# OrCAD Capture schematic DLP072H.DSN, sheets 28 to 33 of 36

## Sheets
28 PAGE33 - SECONDARY PWR & CAP: size A2
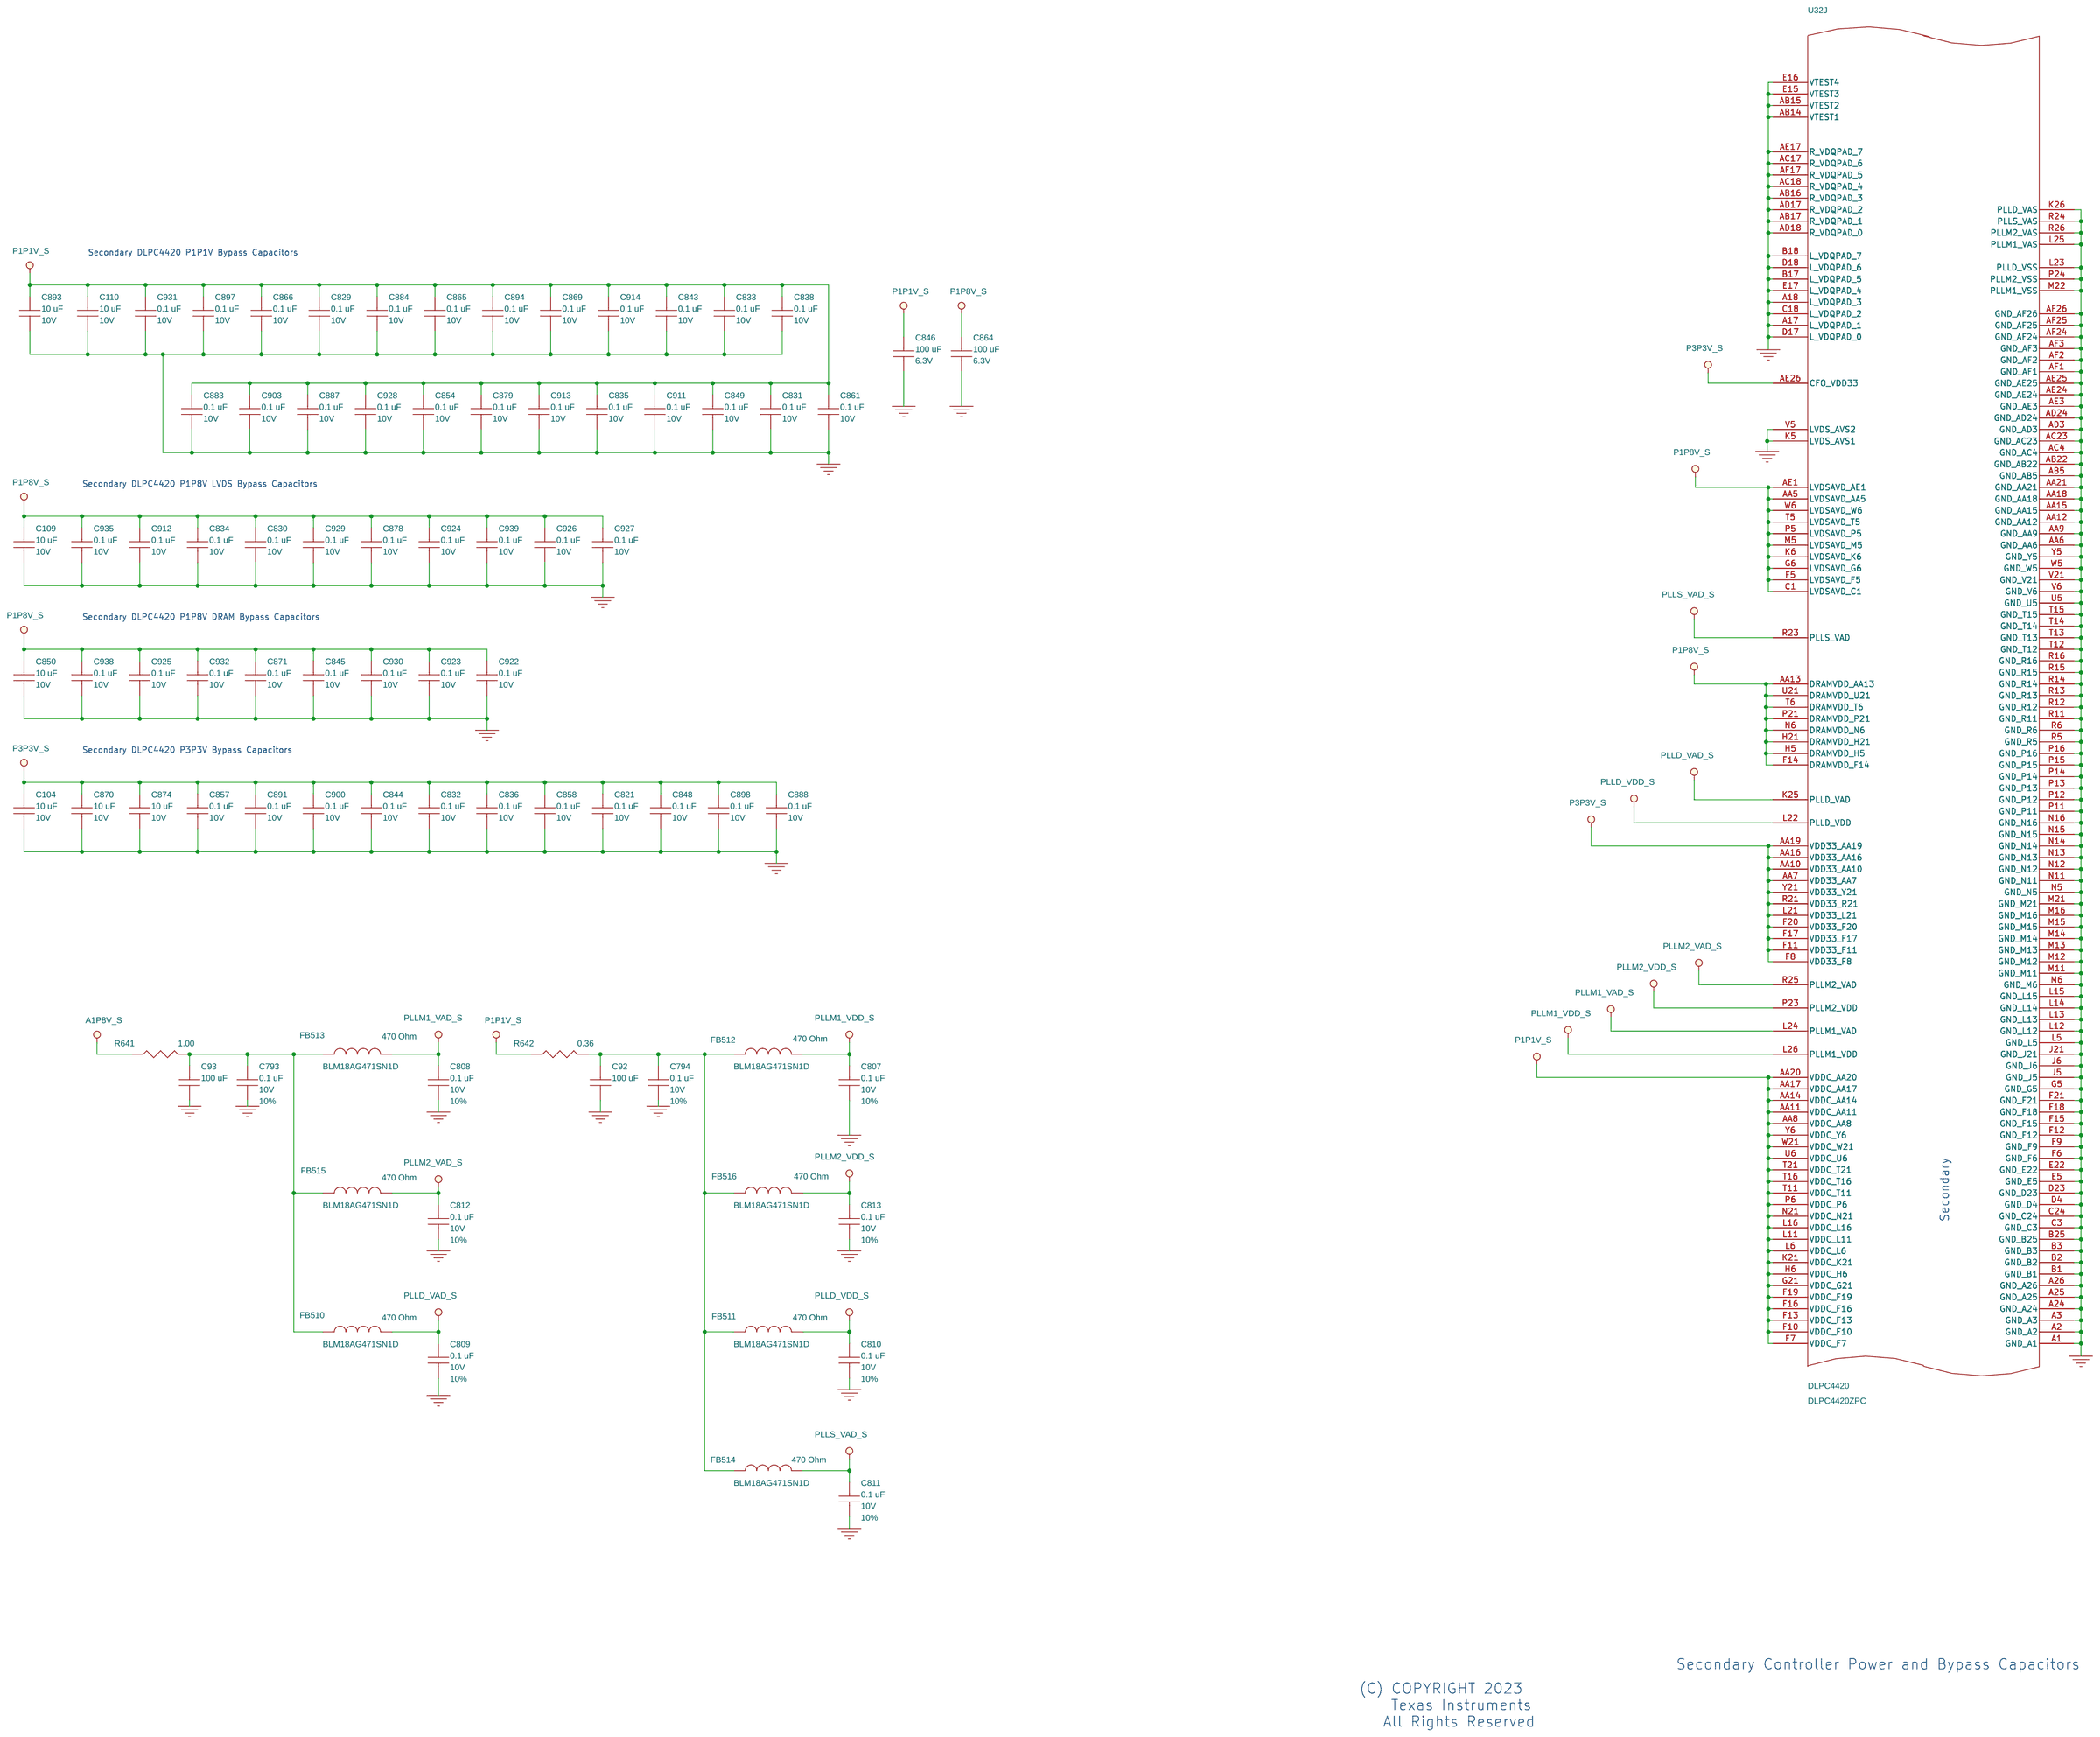
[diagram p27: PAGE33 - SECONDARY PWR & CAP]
29 PAGE36 - IMPORTANT NOTICE
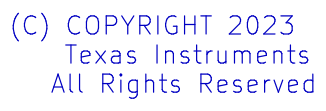
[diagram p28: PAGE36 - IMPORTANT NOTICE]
30 PAGE03 - FPGA FRONT END I/F: size A3
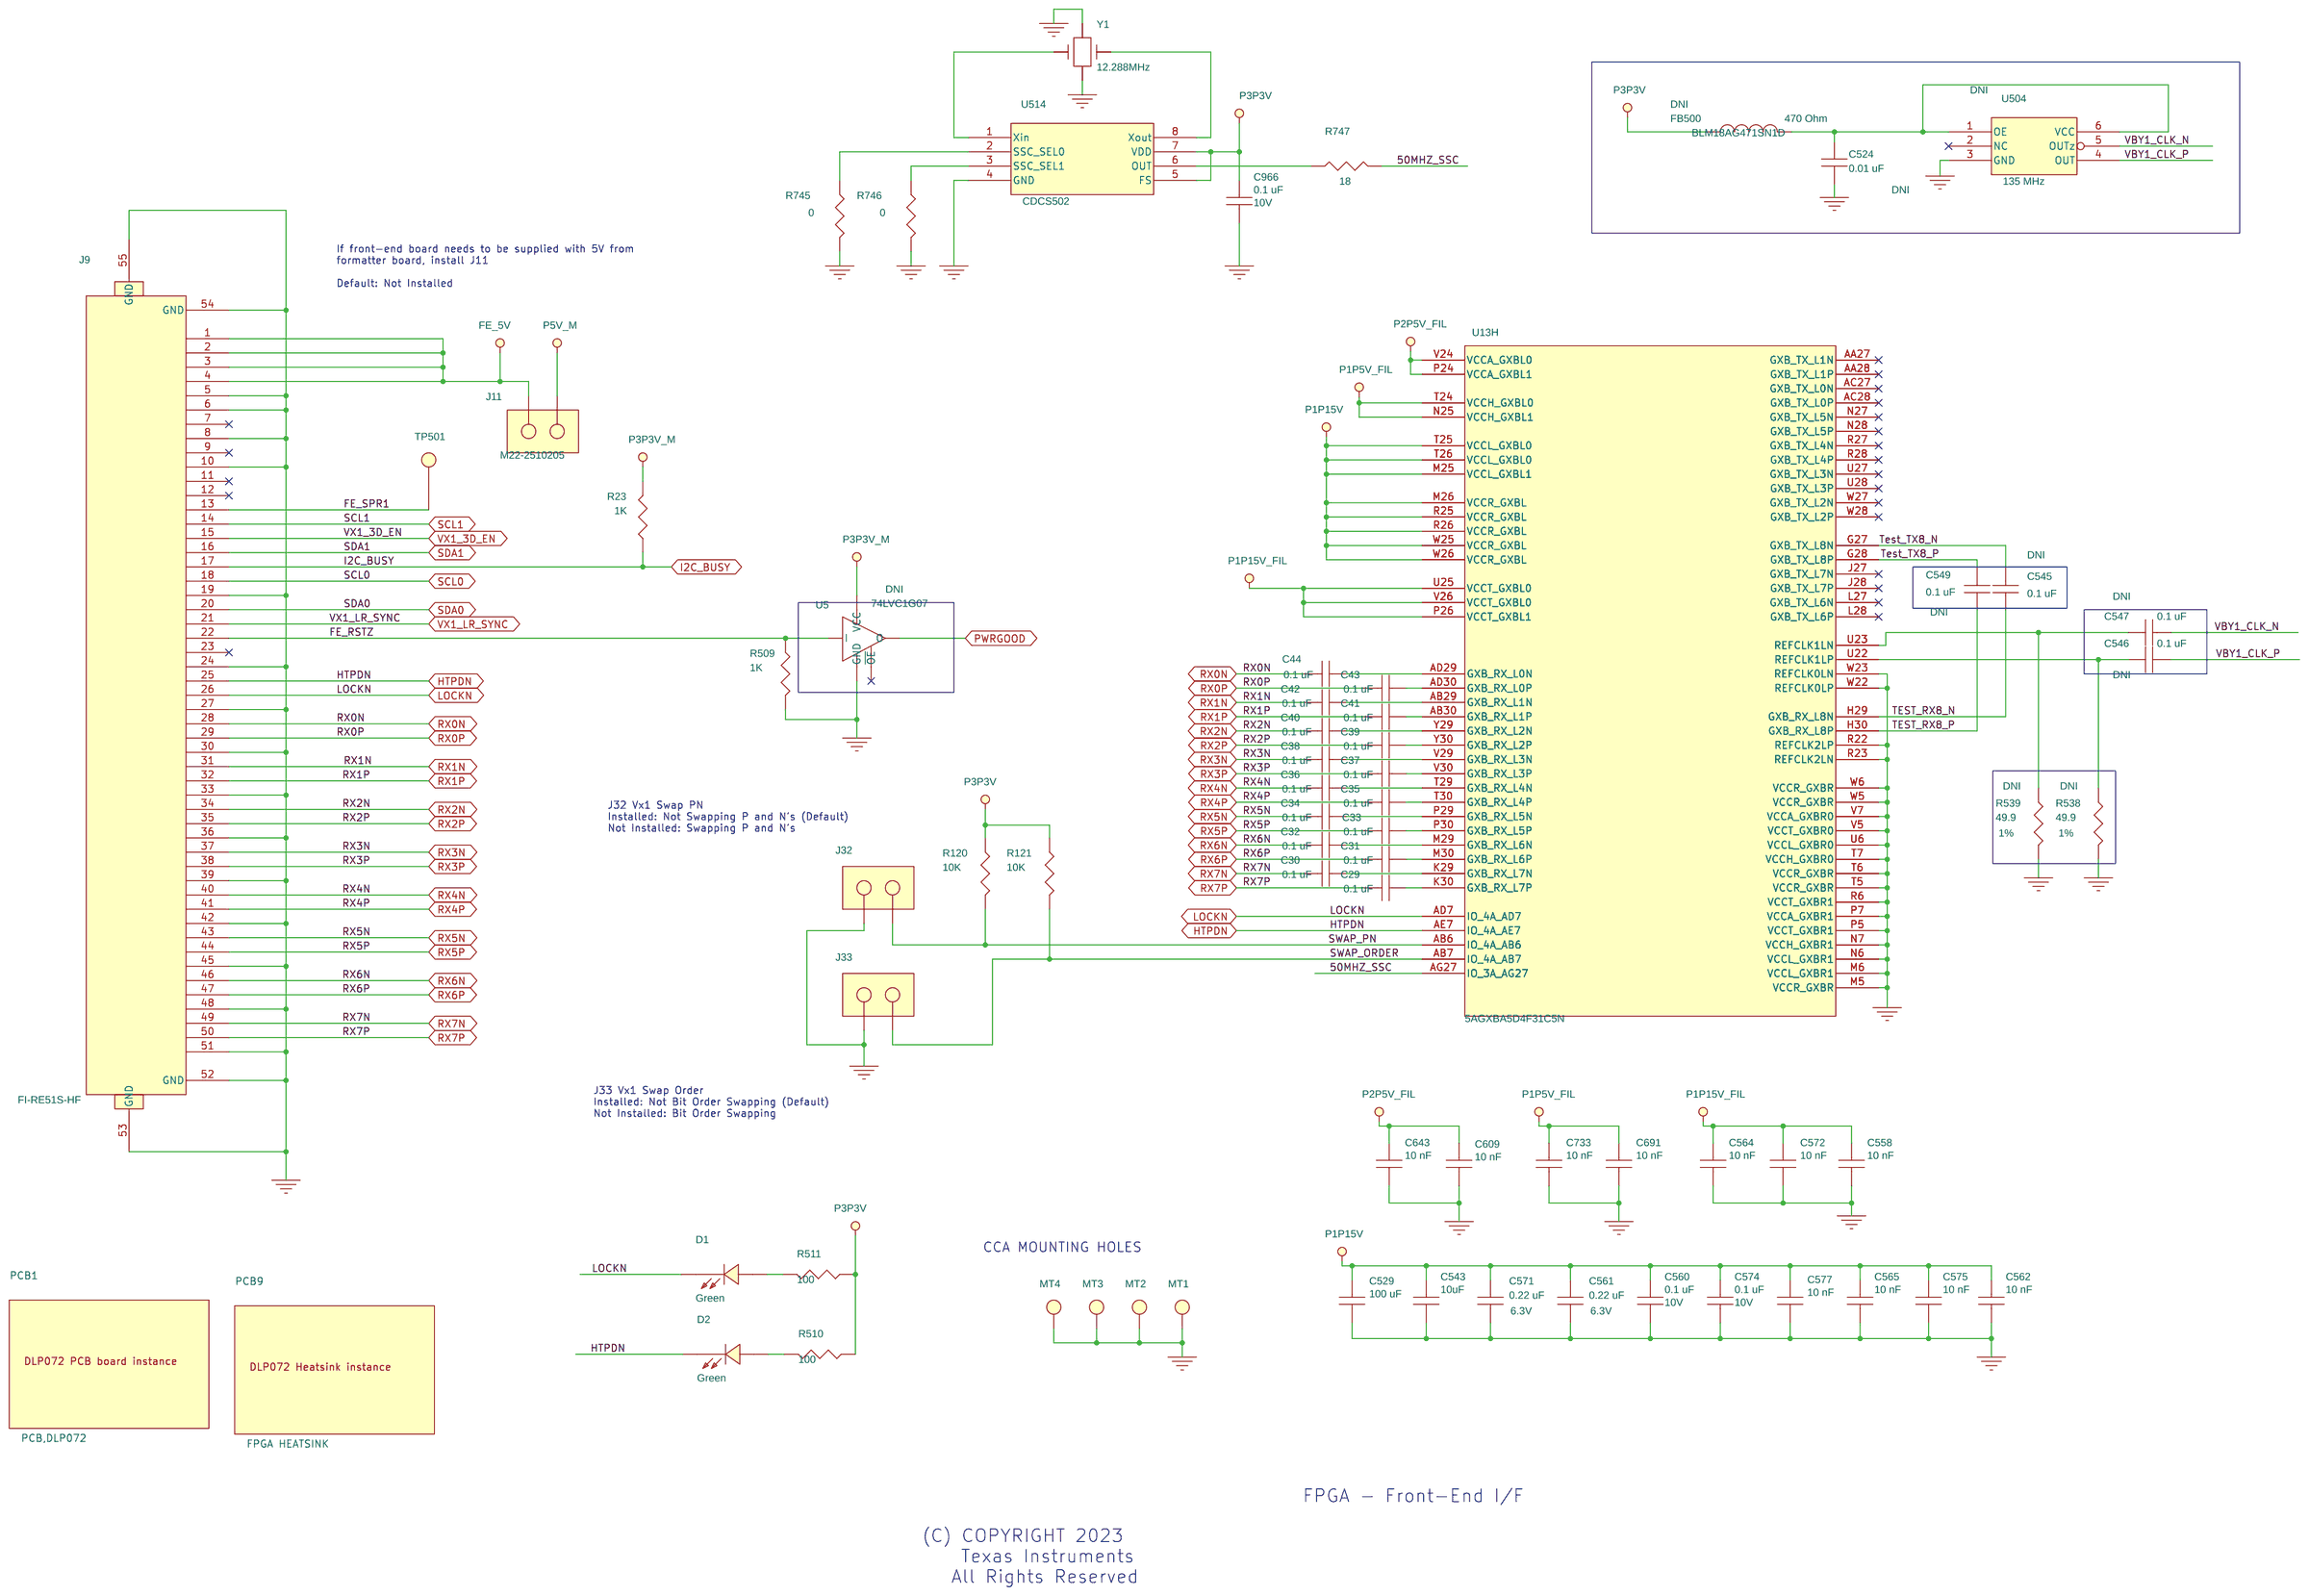
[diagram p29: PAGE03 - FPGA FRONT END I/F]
31 PAGE07 - FPGA Video I/F: size A3
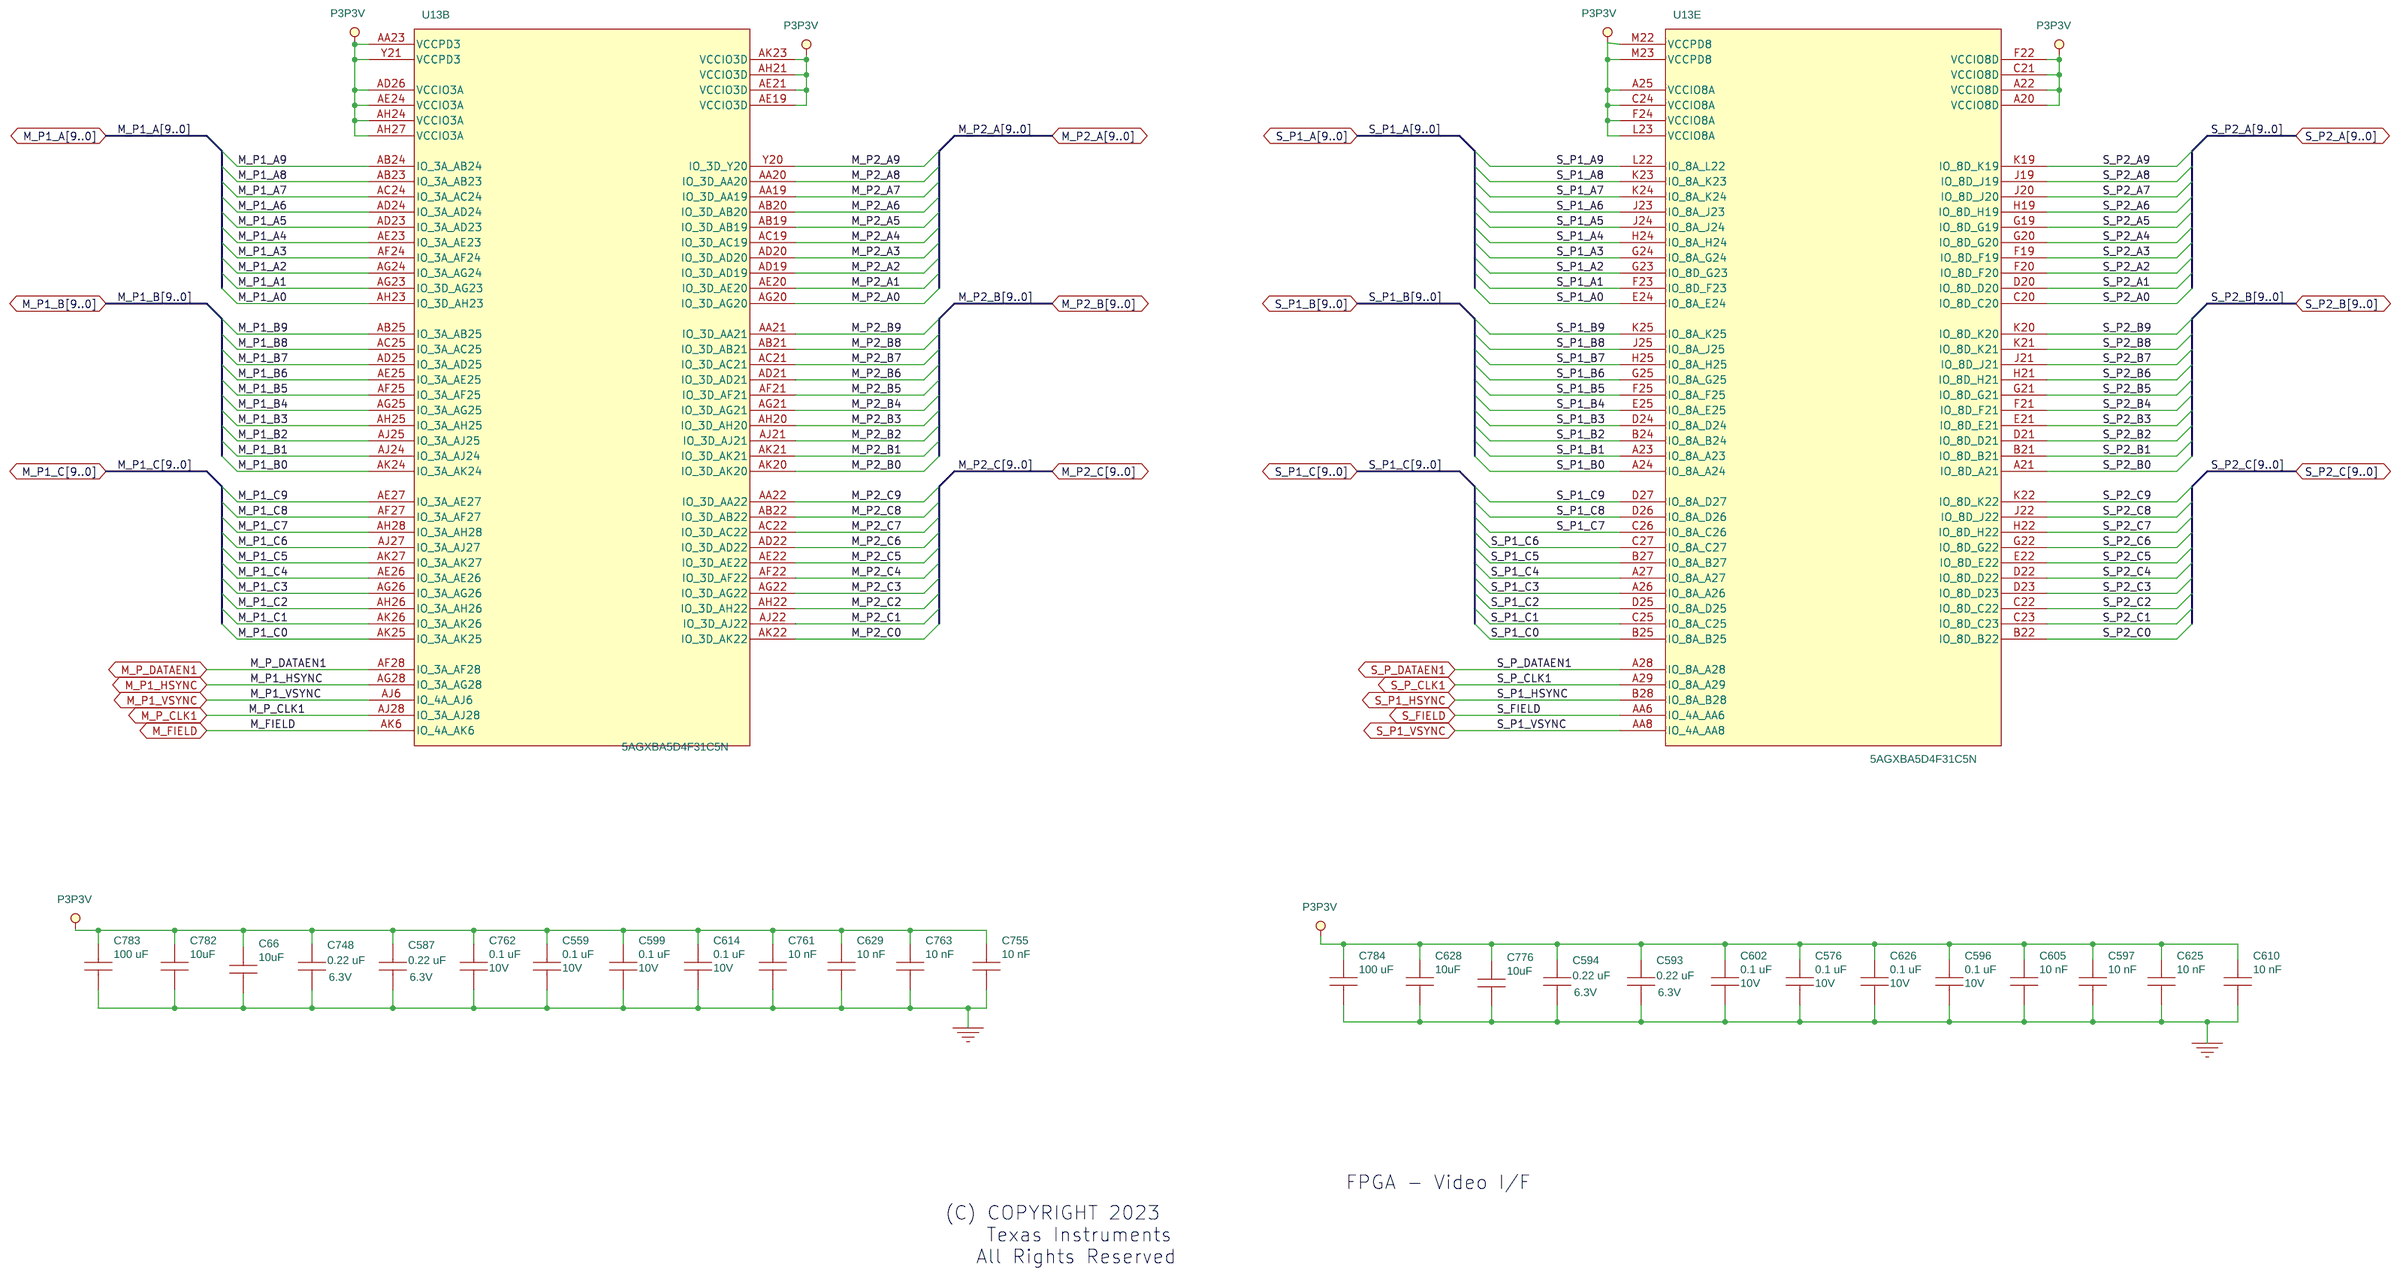
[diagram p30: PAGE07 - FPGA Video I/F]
32 PAGE04 - FPGA DDR3 I/F: size A3
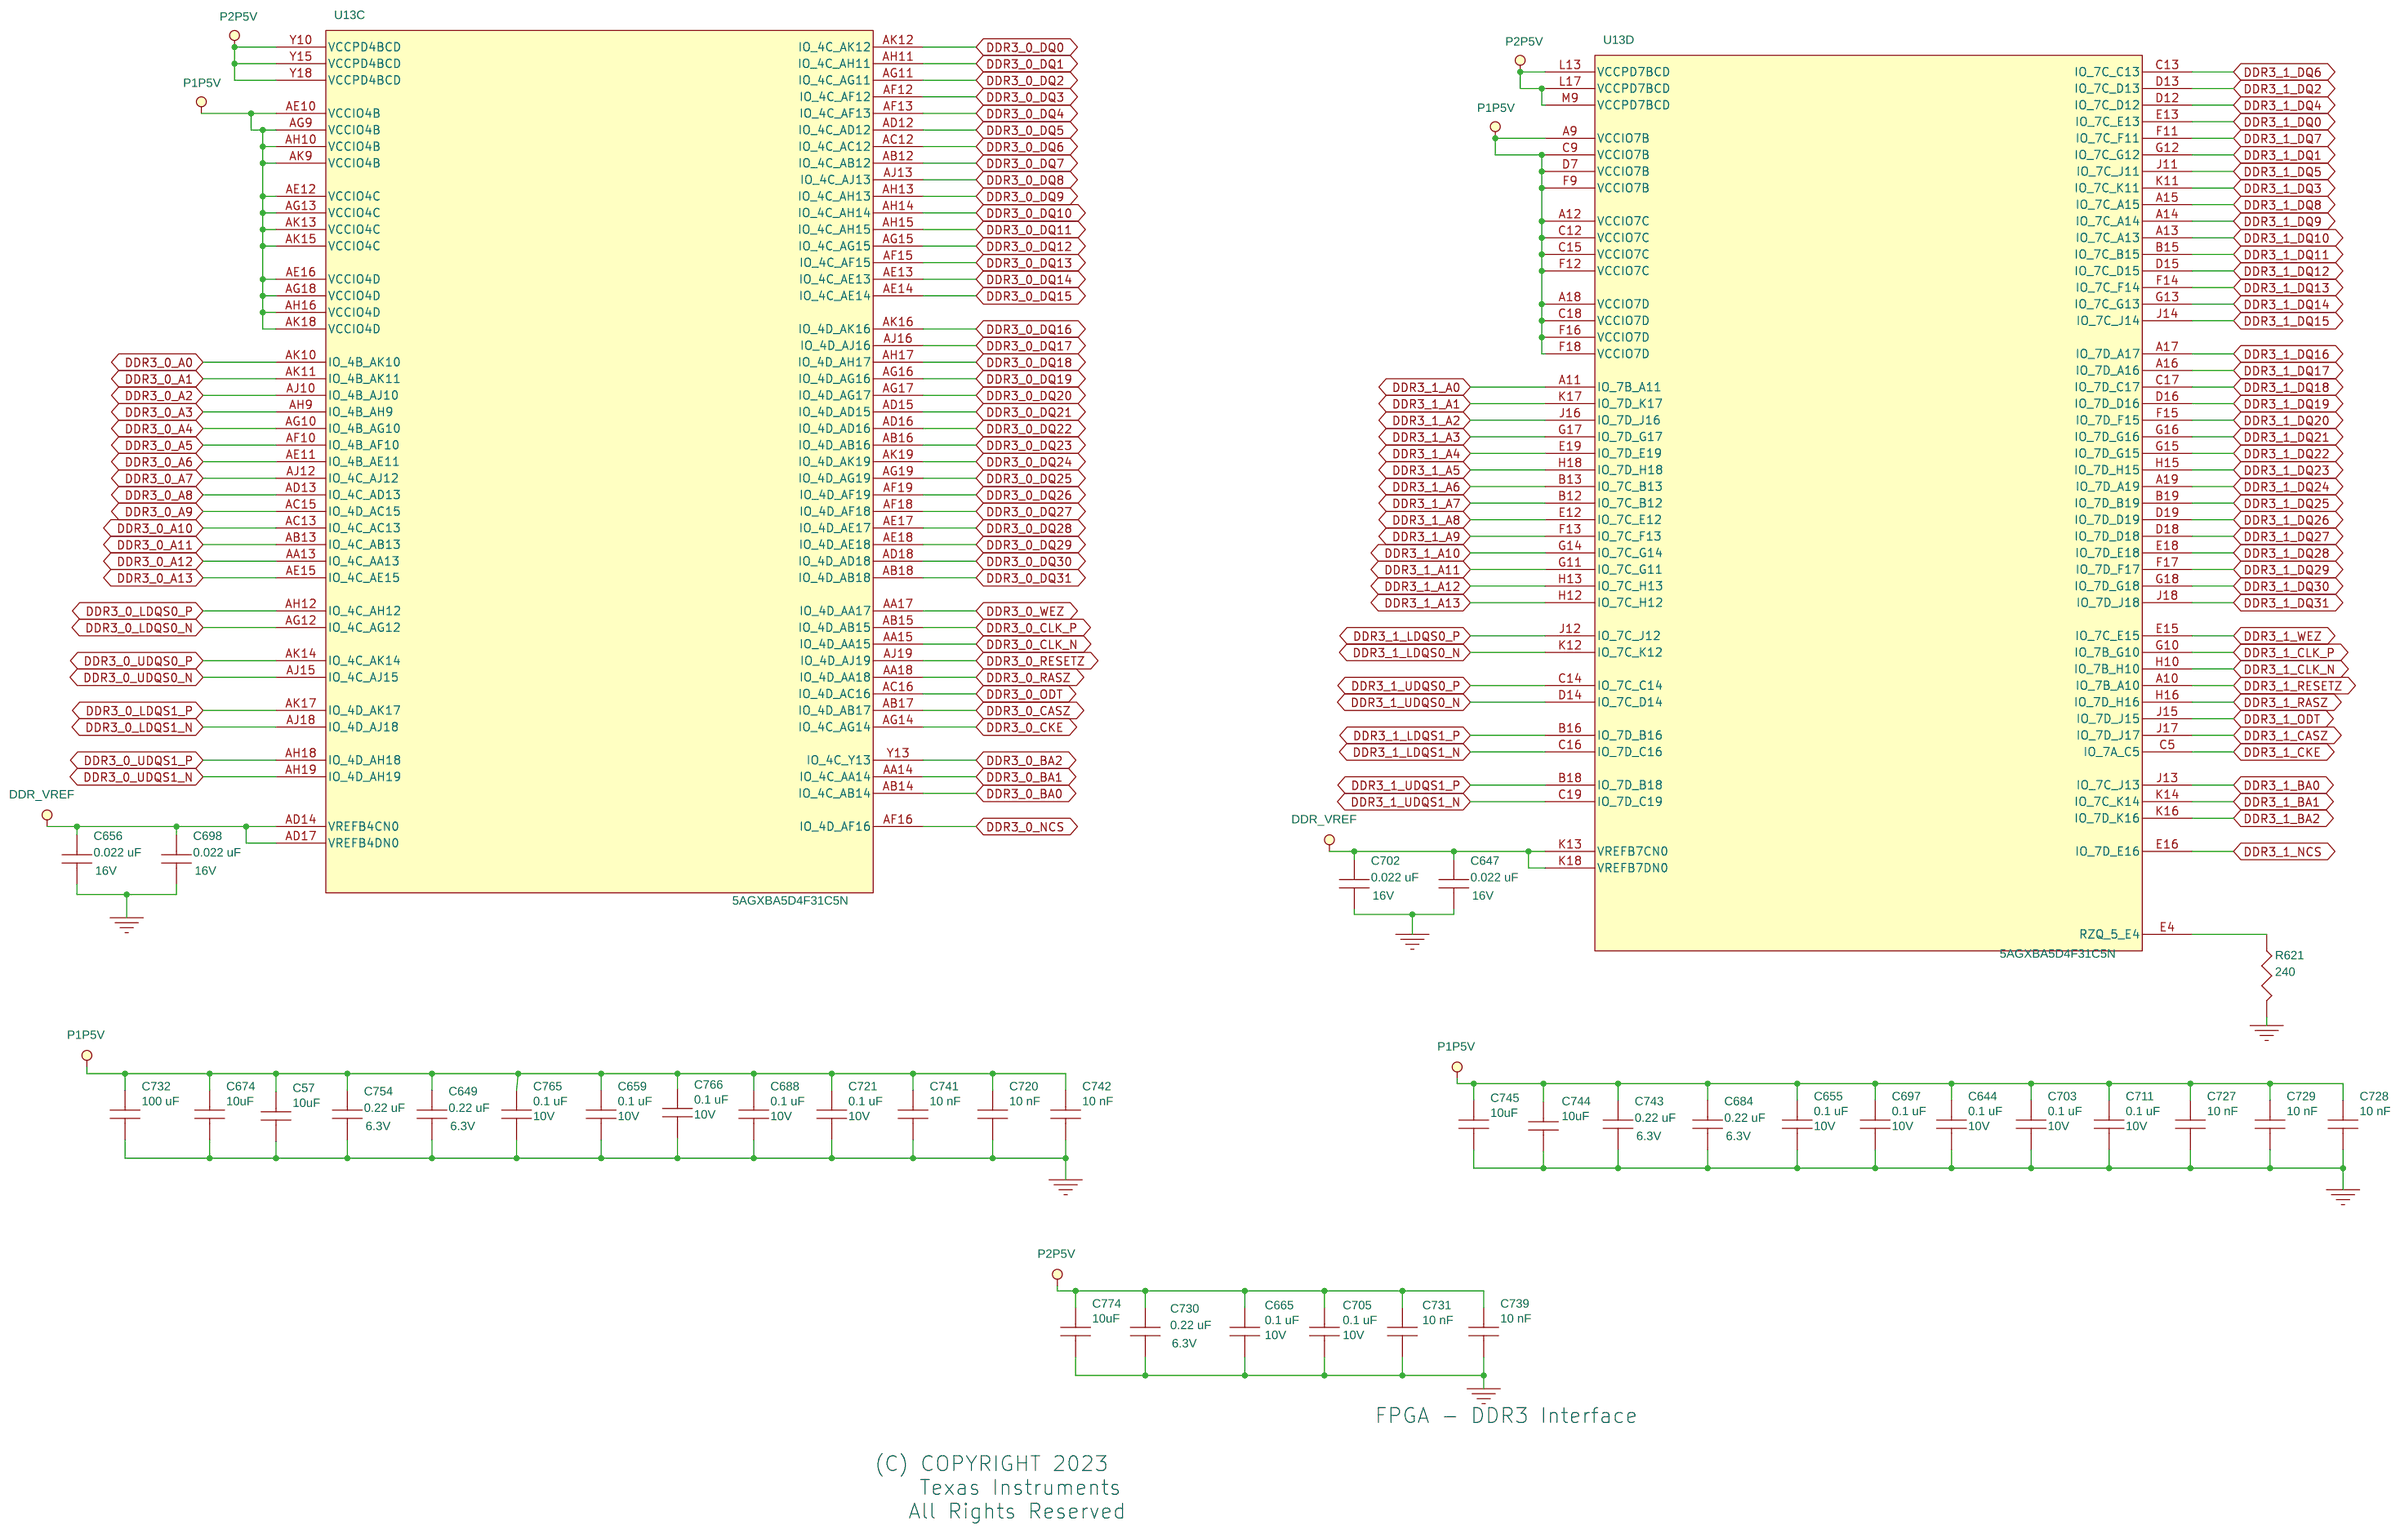
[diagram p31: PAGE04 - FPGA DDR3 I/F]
33 PAGE08 - FPGA Prog/Test MUX: size A3
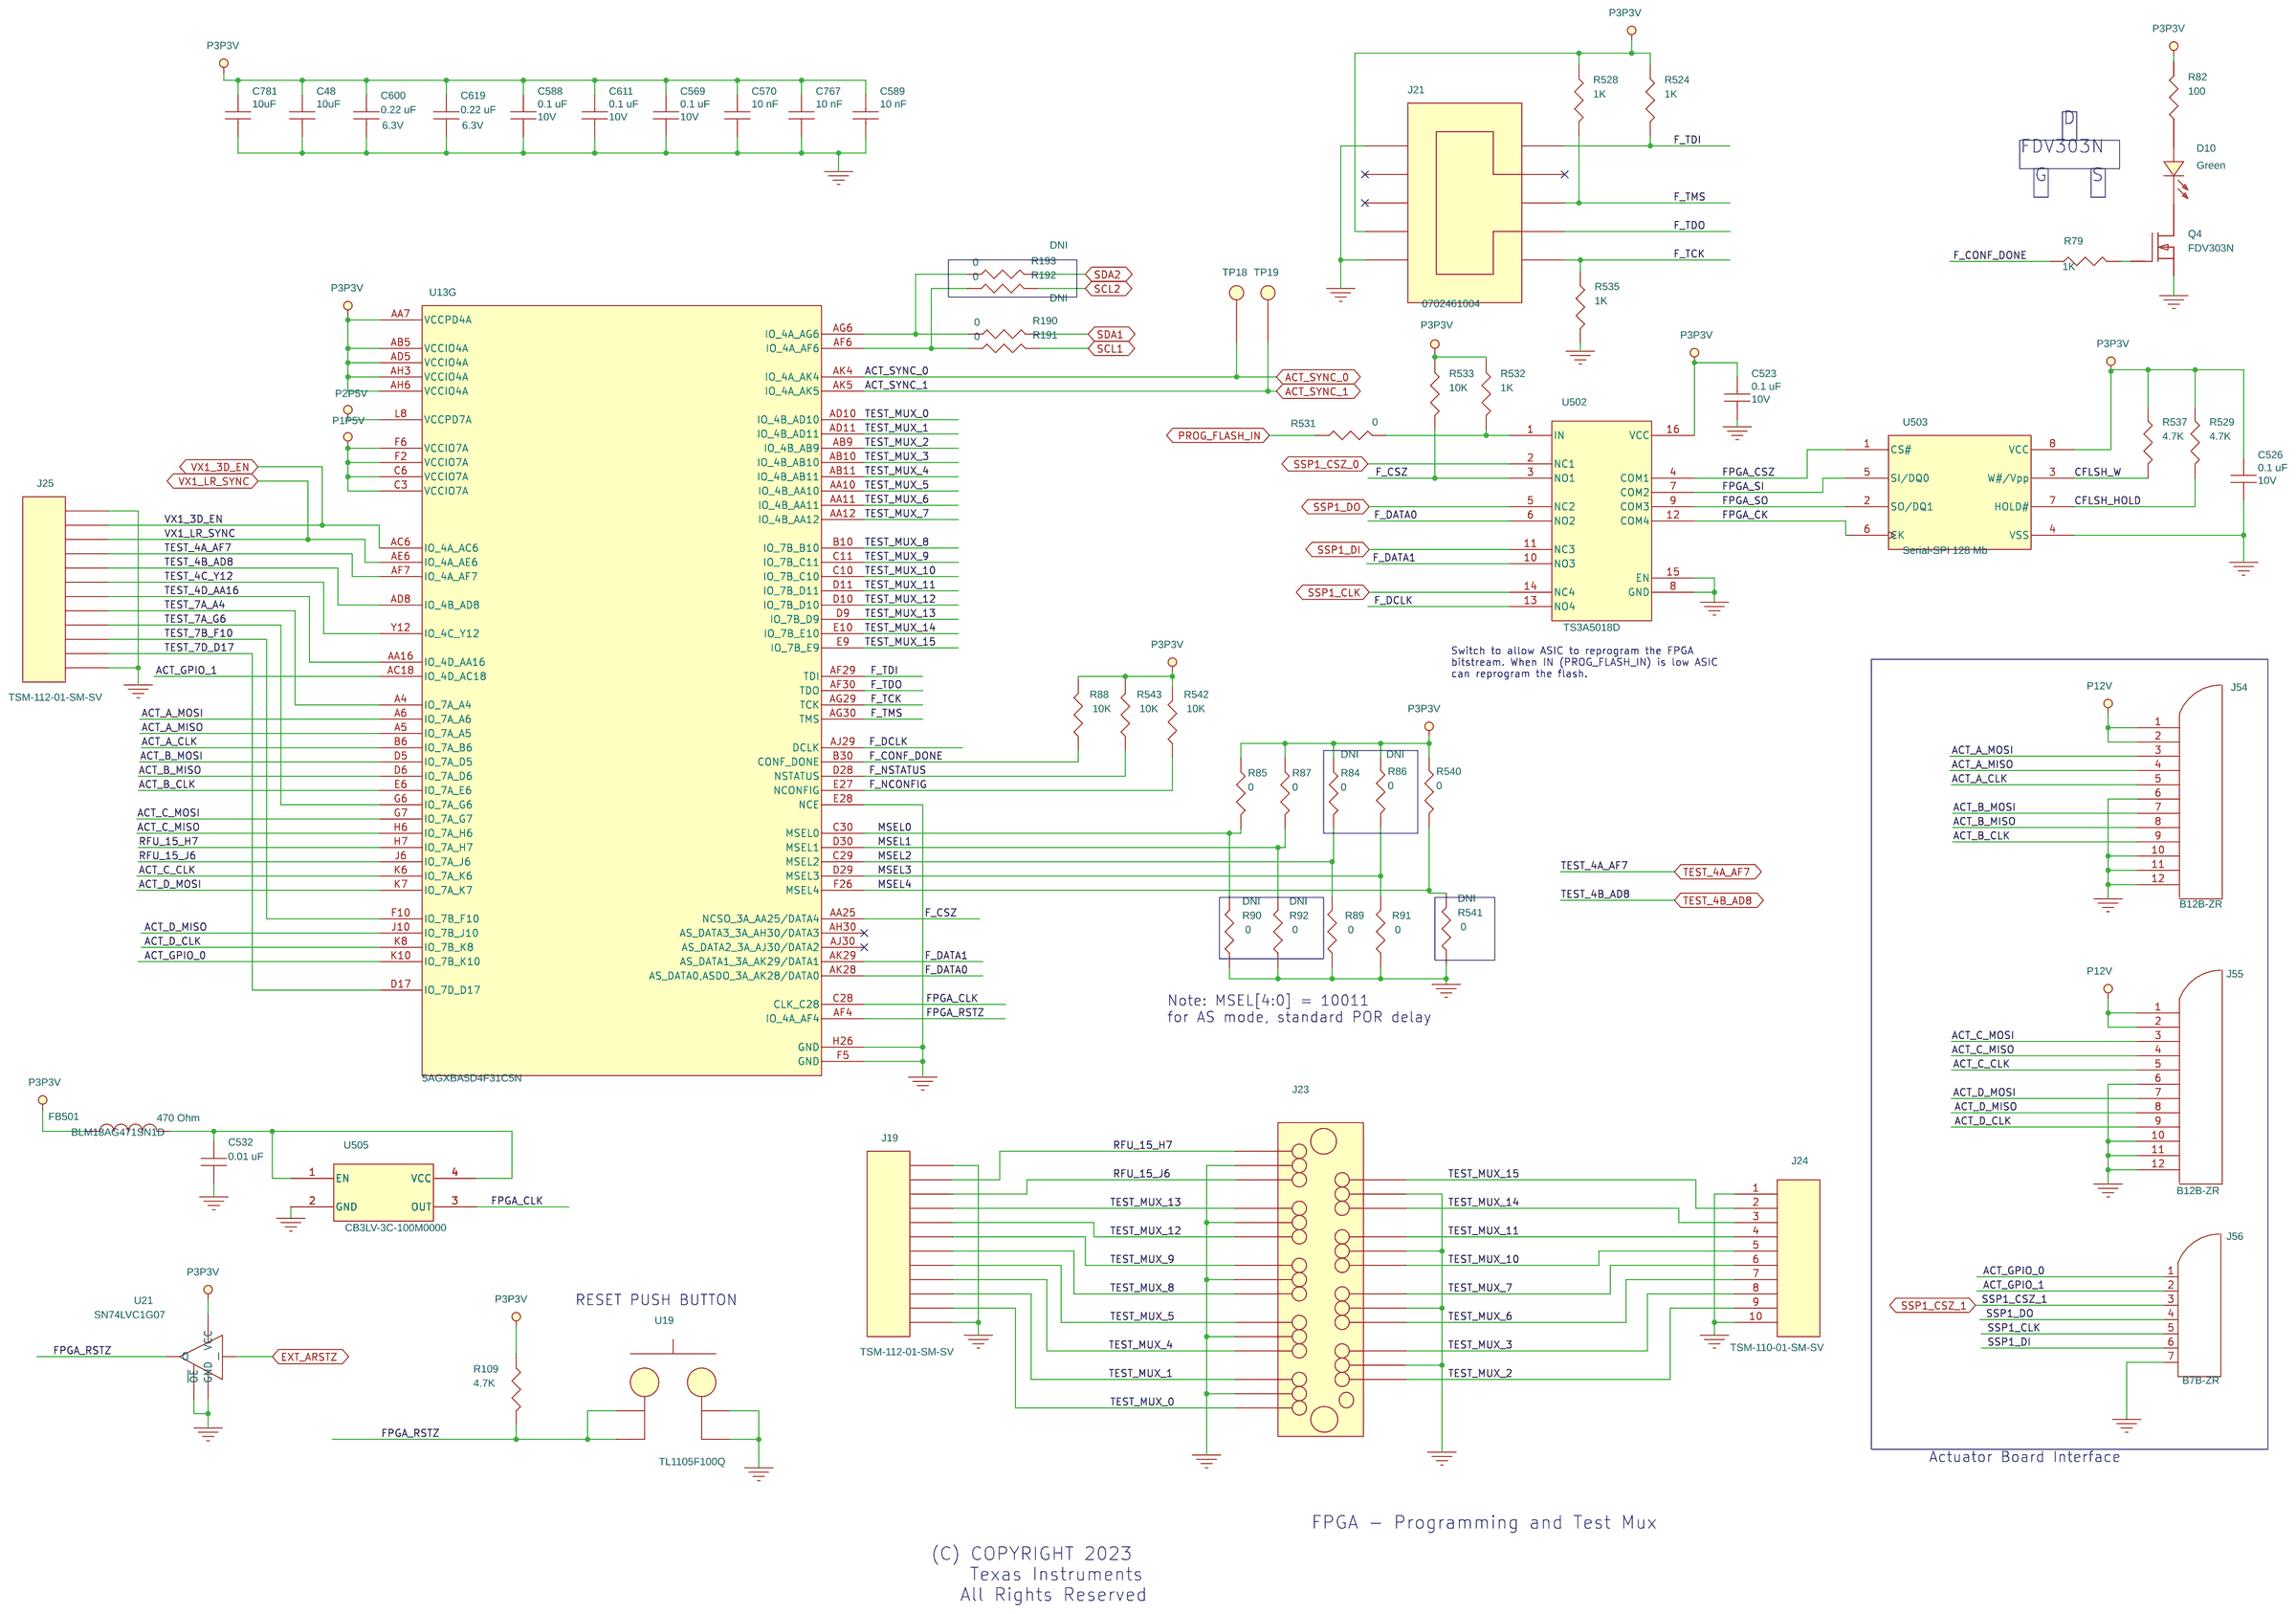
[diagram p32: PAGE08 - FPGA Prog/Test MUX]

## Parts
sheet PAGE03 - FPGA FRONT END I/F
C29  0.1 uF  [CAP_0402]
C30  0.1 uF  [CAP_0402]
C31  0.1 uF  [CAP_0402]
C32  0.1 uF  [CAP_0402]
C33  0.1 uF  [CAP_0402]
C34  0.1 uF  [CAP_0402]
C35  0.1 uF  [CAP_0402]
C36  0.1 uF  [CAP_0402]
C37  0.1 uF  [CAP_0402]
C38  0.1 uF  [CAP_0402]
C39  0.1 uF  [CAP_0402]
C40  0.1 uF  [CAP_0402]
C41  0.1 uF  [CAP_0402]
C42  0.1 uF  [CAP_0402]
C43  0.1 uF  [CAP_0402]
C44  0.1 uF  [CAP_0402]
C524  0.01 uF  [CAP_0603]
C529  100 uF  [CAP_1206]
C543  10uF  [CAP_0402]
C545  0.1 uF  [CAP_0402]
C546  0.1 uF  [CAP_0402]
C547  0.1 uF  [CAP_0402]
C549  0.1 uF  [CAP_0402]
C558  10 nF  [CAP_0402]
C560  0.1 uF  [CAP_0402]
C561  0.22 uF  [CAP_0402]
C562  10 nF  [CAP_0402]
C564  10 nF  [CAP_0402]
C565  10 nF  [CAP_0402]
C571  0.22 uF  [CAP_0402]
C572  10 nF  [CAP_0402]
C574  0.1 uF  [CAP_0402]
C575  10 nF  [CAP_0402]
C577  10 nF  [CAP_0402]
C609  10 nF  [CAP_0402]
C643  10 nF  [CAP_0402]
C691  10 nF  [CAP_0402]
C733  10 nF  [CAP_0402]
C966  0.1 uF  [CAP_0402]
D1  Green  [D_0603]
D2  Green  [D_0603]
FB500  470 Ohm  [FLTR_0603]
J9  FI-RE51S-HF  [FI-R51-RA]
J11  HDR_2  [HDR2_2MM]
J32  HDR_2  [HDR2_2MM]
J33  HDR_2  [HDR2_2MM]
MT1  MOUNTING HOLE  [MH276-157GND]
MT2  MOUNTING HOLE  [MH276-157GND]
MT3  MOUNTING HOLE  [MH276-157GND]
MT4  MOUNTING HOLE  [MH276-157GND]
PCB1  PCB,DLP072
PCB9  FPGA HEATSINK
R23  1K  [RES_0402]
R120  10K  [RES_0402]
R121  10K  [RES_0402]
R509  1K  [RES_0402]
R510  100  [RES_0402]
R511  100  [RES_0402]
R538  49.9  [RES_0402]
R539  49.9  [RES_0402]
R745  0  [RES_0402]
R746  0  [RES_0402]
R747  18  [RES_0402]
TP501  Testpoint  [TP]
U5  74LVC1G07  [SOT23-DBV_TI]
U504  135 MHz  [5x7_6pad]
U514  CDCS502  [8-TSSOP]
Y1  12.288MHz  [ABM8G-12p288MHZ-4Y-T3]
sheet PAGE04 - FPGA DDR3 I/F
C57  10uF  [CAP_0402]
C644  0.1 uF  [CAP_0402]
C647  0.022 uF  [CAP_0402]
C649  0.22 uF  [CAP_0402]
C655  0.1 uF  [CAP_0402]
C656  0.022 uF  [CAP_0402]
C659  0.1 uF  [CAP_0402]
C665  0.1 uF  [CAP_0402]
C674  10uF  [CAP_0402]
C684  0.22 uF  [CAP_0402]
C688  0.1 uF  [CAP_0402]
C697  0.1 uF  [CAP_0402]
C698  0.022 uF  [CAP_0402]
C702  0.022 uF  [CAP_0402]
C703  0.1 uF  [CAP_0402]
C705  0.1 uF  [CAP_0402]
C711  0.1 uF  [CAP_0402]
C720  10 nF  [CAP_0402]
C721  0.1 uF  [CAP_0402]
C727  10 nF  [CAP_0402]
C728  10 nF  [CAP_0402]
C729  10 nF  [CAP_0402]
C730  0.22 uF  [CAP_0402]
C731  10 nF  [CAP_0402]
C732  100 uF  [CAP_1206]
C739  10 nF  [CAP_0402]
C741  10 nF  [CAP_0402]
C742  10 nF  [CAP_0402]
C743  0.22 uF  [CAP_0402]
C744  10uF  [CAP_0402]
C745  10uF  [CAP_0402]
C754  0.22 uF  [CAP_0402]
C765  0.1 uF  [CAP_0402]
C766  0.1 uF  [CAP_0402]
C774  10uF  [CAP_0402]
R621  240  [RES_0402]
sheet PAGE07 - FPGA Video I/F
C66  10uF  [CAP_0402]
C559  0.1 uF  [CAP_0402]
C576  0.1 uF  [CAP_0402]
C587  0.22 uF  [CAP_0402]
C593  0.22 uF  [CAP_0402]
C594  0.22 uF  [CAP_0402]
C596  0.1 uF  [CAP_0402]
C597  10 nF  [CAP_0402]
C599  0.1 uF  [CAP_0402]
C602  0.1 uF  [CAP_0402]
C605  10 nF  [CAP_0402]
C610  10 nF  [CAP_0402]
C614  0.1 uF  [CAP_0402]
C625  10 nF  [CAP_0402]
C626  0.1 uF  [CAP_0402]
C628  10uF  [CAP_0402]
C629  10 nF  [CAP_0402]
C748  0.22 uF  [CAP_0402]
C755  10 nF  [CAP_0402]
C761  10 nF  [CAP_0402]
C762  0.1 uF  [CAP_0402]
C763  10 nF  [CAP_0402]
C776  10uF  [CAP_0402]
C782  10uF  [CAP_0402]
C783  100 uF  [CAP_1206]
C784  100 uF  [CAP_1206]
sheet PAGE08 - FPGA Prog/Test MUX
C48  10uF  [CAP_0402]
C523  0.1 uF  [CAP_0402]
C526  0.1 uF  [CAP_0402]
C532  0.01 uF  [CAP_0603]
C569  0.1 uF  [CAP_0402]
C570  10 nF  [CAP_0402]
C588  0.1 uF  [CAP_0402]
C589  10 nF  [CAP_0402]
C600  0.22 uF  [CAP_0402]
C611  0.1 uF  [CAP_0402]
C619  0.22 uF  [CAP_0402]
C767  10 nF  [CAP_0402]
C781  10uF  [CAP_0402]
D10  Green  [D_0603]
FB501  470 Ohm  [FLTR_0603]
J19  CON12  [CONN12-SMT-TSM-112-SV_SAMTEC]
J21  0702461004  [10POS-2ROWS-2p54mm]
J23  EM,CONN,P6419 Footprint  [TEKP6419]
J24  TSM-110-01-SM-SV  [CN-10-2_54MM]
J25  CON12  [CONN12-SMT-TSM-112-SV_SAMTEC]
J54  B12B-ZR  [B12B-ZR]
J55  B12B-ZR  [B12B-ZR]
J56  B7B-ZR  [B7B-ZR]
Q4  FDV303N  [SOT-23]
R79  1K  [RES_0402]
R82  100  [RES_0402]
R84  0  [RES_0402]
R85  0  [RES_0402]
R86  0  [RES_0402]
R87  0  [RES_0402]
R88  10K  [RES_0402]
R89  0  [RES_0402]
R90  0  [RES_0402]
R91  0  [RES_0402]
R92  0  [RES_0402]
R109  4.7K  [RES_0402]
R190  0  [RES_0402]
R191  0  [RES_0402]
R192  0  [RES_0402]
R193  0  [RES_0402]
R524  1K  [RES_0402]
R528  1K  [RES_0402]
R529  4.7K  [RES_0402]
R531  0  [RES_0402]
R532  1K  [RES_0402]
R533  10K  [RES_0402]
R535  1K  [RES_0402]
R537  4.7K  [RES_0402]
R540  0  [RES_0402]
R541  0  [RES_0402]
R542  10K  [RES_0402]
R543  10K  [RES_0402]
TP18  Testpoint  [TP]
TP19  Testpoint  [TP]
U19  6MM PUSH BUTTON SWITCH  [SW4-TL1105_ESWITCH]
U21  SN74LVC1G07  [SOT23-DBV_TI]
U502  TS3A5018D  [SOIC-16]
U503  Serial-SPI 128 Mb  [SO8W]
U505  CB3LV-3C-100M0000  [5x7mm]
sheet PAGE09 - FPGA POWER
U13  5AGXBA5D4F31C5N  [FBGA-896]  (sections A,B,C,D,E,F,G,H,I)
sheet PAGE16 - INPUT PWR & PMD1000
U32  DLPC4420  [BGA552-DDP4422_TI]  (sections A,B,C,D,E,F,G,H,I,J)
sheet PAGE33 - SECONDARY PWR & CAP
C92  100 uF  [CAP_1206]
C93  100 uF  [CAP_1206]
C104  10 uF  [CAP_0805]
C109  10 uF  [CAP_0805]
C110  10 uF  [CAP_0805]
C793  0.1 uF  [CAP_0402]
C794  0.1 uF  [CAP_0402]
C807  0.1 uF  [CAP_0402]
C808  0.1 uF  [CAP_0402]
C809  0.1 uF  [CAP_0402]
C810  0.1 uF  [CAP_0402]
C811  0.1 uF  [CAP_0402]
C812  0.1 uF  [CAP_0402]
C813  0.1 uF  [CAP_0402]
C821  0.1 uF  [CAP_0402]
C829  0.1 uF  [CAP_0402]
C830  0.1 uF  [CAP_0402]
C831  0.1 uF  [CAP_0402]
C832  0.1 uF  [CAP_0402]
C833  0.1 uF  [CAP_0402]
C834  0.1 uF  [CAP_0402]
C835  0.1 uF  [CAP_0402]
C836  0.1 uF  [CAP_0402]
C838  0.1 uF  [CAP_0402]
C843  0.1 uF  [CAP_0402]
C844  0.1 uF  [CAP_0402]
C845  0.1 uF  [CAP_0402]
C846  100 uF  [CAP_1206]
C848  0.1 uF  [CAP_0402]
C849  0.1 uF  [CAP_0402]
C850  10 uF  [CAP_0805]
C854  0.1 uF  [CAP_0402]
C857  0.1 uF  [CAP_0402]
C858  0.1 uF  [CAP_0402]
C861  0.1 uF  [CAP_0402]
C864  100 uF  [CAP_1206]
C865  0.1 uF  [CAP_0402]
C866  0.1 uF  [CAP_0402]
C869  0.1 uF  [CAP_0402]
C870  10 uF  [CAP_0805]
C871  0.1 uF  [CAP_0402]
C874  10 uF  [CAP_0805]
C878  0.1 uF  [CAP_0402]
C879  0.1 uF  [CAP_0402]
C883  0.1 uF  [CAP_0402]
C884  0.1 uF  [CAP_0402]
C887  0.1 uF  [CAP_0402]
C888  0.1 uF  [CAP_0402]
C891  0.1 uF  [CAP_0402]
C893  10 uF  [CAP_0805]
C894  0.1 uF  [CAP_0402]
C897  0.1 uF  [CAP_0402]
C898  0.1 uF  [CAP_0402]
C900  0.1 uF  [CAP_0402]
C903  0.1 uF  [CAP_0402]
C911  0.1 uF  [CAP_0402]
C912  0.1 uF  [CAP_0402]
C913  0.1 uF  [CAP_0402]
C914  0.1 uF  [CAP_0402]
C922  0.1 uF  [CAP_0402]
C923  0.1 uF  [CAP_0402]
C924  0.1 uF  [CAP_0402]
C925  0.1 uF  [CAP_0402]
C926  0.1 uF  [CAP_0402]
C927  0.1 uF  [CAP_0402]
C928  0.1 uF  [CAP_0402]
C929  0.1 uF  [CAP_0402]
C930  0.1 uF  [CAP_0402]
C931  0.1 uF  [CAP_0402]
C932  0.1 uF  [CAP_0402]
C935  0.1 uF  [CAP_0402]
C938  0.1 uF  [CAP_0402]
C939  0.1 uF  [CAP_0402]
FB510  470 Ohm  [FLTR_0603]
FB511  470 Ohm  [FLTR_0603]
FB512  470 Ohm  [FLTR_0603]
FB513  470 Ohm  [FLTR_0603]
FB514  470 Ohm  [FLTR_0603]
FB515  470 Ohm  [FLTR_0603]
FB516  470 Ohm  [FLTR_0603]
R641  1.00  [RES_0402]
R642  0.36  [RES_0402]

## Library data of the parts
C29-C44 C559 C560 C569 C574 C576 C588 C596 C599 C602 C611 C614 C626 C644 C655 C659 C665 C688 C697 C703 C705 C711 C721 C762 C765 C766 = CER_0.1UF_16V_10%_X5R_0402: CCA: 34; MFG: KEMET; Part Number: C0402C104K8RACTU; Rating: 10V; SOURCE: DIGI 399-3520-1-ND; Type: X7R
C524 = CAP_NP: Capacitor; CCA: 47; DNI: DNI; MFG: YAGEO; Part Number: CC0603KRX7R8BB103; RATING: 25V; TOLERANCE: 10%; Type: X7R
C529 C732 C783 C784 = CER_100UF_6.3V_20%_X5R_1206: CCA: 114; MFG: KEMET; Part Number: C1206C107M9PACTU; Type: X5R
C48 C57 C66 C543 C628 C674 C744 C745 C774 C776 C781 C782 = CER_10UF_6.3V_20%_X5R_0402: Part Number: CL05A106MQ5NUNC
C545-C547 C549 = CER_0.1UF_16V_10%_X5R_0402: CCA: 34; DNI: DNI; MFG: KEMET; Part Number: C0402C104K8RACTU; Rating: 10V; SOURCE: DIGI 399-3520-1-ND; Type: X7R
C558 C562 C564 C565 C570 C572 C575 C577 C589 C597 C605 C609 C610 C625 C629 C643 C691 C720 C727-C729 C731 C733 C739 C741 C742 C755 C761 C763 C767 = CER_10_nF_25V_10%_X5R_0402: Part Number: C1005X7R1H103K050BB
C561 C571 C587 C593 C594 C600 C619 C649 C684 C730 C743 C748 C754 = CAP_NP: Capacitor; CCA: 39; MFG: SAMSUNG; Part Number: CL05A224KQ5NNNC; RATING: 6.3V; SOURCE: DIGI 399-3491-1-ND; TOLERANCE: 10%; Type: X5R
C523 C526 C966 = CER_0.1UF_16V_10%_X5R_0402: CCA: 34; MFG: KEMET; Part Number: C0402C104K8RACTU; Rating: 10V; Type: X7R
D1 D2 D10 = LED_GREEN_CLEAR_0603: LED; Part Number: LTST-C190GKT
FB500 = INDUCTOR: Ferrite; CCA: 30; DNI: DNI; ICA_MFR_NAME: STEWARD; ICA_PARTNUM: $$731362$$MI0603J680R-10; MFG: MURATA; Part Number: BLM18AG471SN1D; RATING: 500mA, 100MHz; SOURCE: DIGI 490-1013-1-ND
J9 = FI-RE51S-HF: Connector, Vby1; MFG: JAE
J11 J32 J33 = HDR_0: Jumper, 1x2; CCA: 128; MFG: HARWIN; Part Number: M22-2510205; SOURCE: DIGI 952-1311-ND
MT1-MT4 = Testpoint_0: Mounting Hole; MFG: NA; Part Number: NA; SOURCE: NA
PCB1 = DLP027_1
PCB9 = DLP027_2
R23 R509 = R: Resistor; CCA: 64; ICA_MFR_NAME: PANASONIC; ICA_PARTNUM: $$1785048$$ERJ-3GSYJ102; MFG: PANASONIC; Part Number: ERJ-2GEJ102X; RATING: 1/10W; SOURCE: DIGI P1.0KJCT-ND; TOLERANCE: 5%
R88 R120 R121 R542 R543 = R: Resistor; CCA: 65; ICA_MFR_NAME: PANASONIC; ICA_PARTNUM: $$1785048$$ERJ-3GSYJ102; MFG: PANASONIC; Part Number: ERJ-2GEJ103X; RATING: 1/10W; SOURCE: DIGI P10.0KLCT-ND; TOLERANCE: 5%
R82 R510 R511 = R: Resistor; CCA: 63; ICA_MFR_NAME: PANASONIC; ICA_PARTNUM: $$1785048$$ERJ-3GSYJ102; MFG: PANASONIC; Part Number: ERJ-2GEJ101X; RATING: 1/10W; SOURCE: DIGI P100JCT-ND; TOLERANCE: 5%
R538 R539 = R: Resistor; DNI: DNI; ICA_MFR_NAME: PANASONIC; ICA_PARTNUM: $$1785048$$ERJ-3GSYJ102; MFG: BOURNS; Part Number: CR0402-FX-49R9GLF; RATING: 1/16 W; SOURCE: DIGI P10.0KLCT-ND; TOLERANCE: 1%
R85 R87 R190 R191 R531 R540 R745 R746 = R: Resistor; CCA: 62; ICA_MFR_NAME: PANASONIC; ICA_PARTNUM: $$1785048$$ERJ-3GSYJ102; MFG: PANASONIC; Part Number: ERJ-2GE0R00X; RATING: 1/10W; SOURCE: DIGI P0.0JCT-ND
R747 = R: Resistor; CCA: 62; ICA_MFR_NAME: PANASONIC; ICA_PARTNUM: $$1785048$$ERJ-3GSYJ102; MFG: PANASONIC; Part Number: ERJ-2GEJ180X; RATING: 1/10W; SOURCE: DIGI P0.0JCT-ND
TP18 TP19 TP501 = Testpoint: Test point
U5 = 74LVC1G07: IC, Non-Inverting Buffer, Open Drain; CCA: 147; DNI: DNI; MFG: TI; Part Number: SN74LVC1G07DBVR; SOURCE: DIGI 296-8485-1-ND
U504 = OSC_LVDS: OSC; DNI: DNI; MFG: ECLIPTEK; Part Number: EQRF13B2H-135.000M; Tolerance: 50 PPM
U514 = CDCS502: IC OSC CLOCK GENERATOR 8-TSSOP; Manuf Part Number: CDCS502PW; Manufacturer: Texas Instruments; Part Number: CDCS502PW
Y1 = CRYSTAL: 12.288MHz ±30ppm Crystal 10pF 80 Ohm -10°C ~ 60°C Surface Mount 4-SMD, No Lead (DFN, LCC); Manuf Part Number: ABM8G-12.288MHZ-4Y-T3; Manufacturer: Abracon; Part Number: ABM8G-12.288MHZ-4Y-T3
C647 C656 C698 C702 = CAP_NP: Capacitor; CCA: 5; MFG: AVX; Part Number: 0402YC223KAT2A; RATING: 16V; TOLERANCE: 10%; Type: X5R
R621 = R: Resistor; ALT_SYMBOLS: 0402-1MM; CCA: 73; ICA_MFR_NAME: PANASONIC; ICA_PARTNUM: $$1785048$$ERJ-3GSYJ102; MFG: PANASONIC; Part Number: ERJ-2RKF2400X; RATING: 1/10W; TOLERANCE: 1%
C532 = CAP_NP: Capacitor; CCA: 47; MFG: YAGEO; Part Number: CC0603KRX7R8BB103; RATING: 25V; TOLERANCE: 10%; Type: X7R
FB501 FB510-FB516 = INDUCTOR: Ferrite; CCA: 30; ICA_MFR_NAME: STEWARD; ICA_PARTNUM: $$731362$$MI0603J680R-10; MFG: MURATA; Part Number: BLM18AG471SN1D; RATING: 500mA, 100MHz; SOURCE: DIGI 490-1013-1-ND
J19 J25 = CON12: Header, 12 pin; CCA: 174; MFG: SAMTEC; Part Number: TSM-112-01-SM-SV; SOURCE: SAMTEC
J21 = 10POS_2ROWS_2.54MM_VERT
J23 = EM,CONN,P6419_Footprint: Conn, Logic Analyzer Footprint
J24 = CONN10: Conn 10 pin; MFG: Samtec; Part Number: TSM-110-01-S-SV
J54 J55 = CONN_1X12PINS: 12 Positions Header, Shrouded Connector 0.059" (1.50mm) Surface Mount Tin; Manuf Part Number: B12B-ZR-SM4-TF(LF)(SN); Manufacturer: JST; Part Number: B12B-ZR(LF)(SN)
J56 = CONN_1X7PINS: 7 Positions Header, Shrouded Connector 0.059" (1.50mm) Surface Mount Tin; Manuf Part Number: B7B-ZR-SM4-TF(LF)(SN); Manufacturer: JST; Part Number: B7B-ZR(LF)(SN)
Q4 = FDV303N_MOSFET_N_0
R79 R524 R528 R532 R535 = 1.0K_OHM_1_16W_5%_0402: CCA: 64; MFG: PANASONIC; Part Number: ERJ-2GEJ102X; Rating: 1/10W
R84 R86 R192 R193 = R: Resistor; CCA: 62; DNI: DNI; ICA_MFR_NAME: PANASONIC; ICA_PARTNUM: $$1785048$$ERJ-3GSYJ102; MFG: PANASONIC; Part Number: ERJ-2GE0R00X; RATING: 1/10W; SOURCE: DIGI P0.0JCT-ND
R89 R91 = R: Resistor; CCA: 65; ICA_MFR_NAME: PANASONIC; ICA_PARTNUM: $$1785048$$ERJ-3GSYJ102; MFG: PANASONIC; Part Number: ERJ-2GE0R00X; RATING: 1/10W; SOURCE: DIGI P0.0JCT-ND; TOLERANCE: 5%
R90 R92 R541 = R: Resistor; CCA: 65; DNI: DNI; ICA_MFR_NAME: PANASONIC; ICA_PARTNUM: $$1785048$$ERJ-3GSYJ102; MFG: PANASONIC; Part Number: ERJ-2GE0R00X; RATING: 1/10W; SOURCE: DIGI P0.0JCT-ND; TOLERANCE: 5%
R109 = R: Resistor; ALT_SYMBOLS: 0402-1MM; CCA: 69; ICA_MFR_NAME: PANASONIC; ICA_PARTNUM: $$1785048$$ERJ-3GSYJ102; MFG: PANASONIC; Part Number: ERJ-2GEJ472X; RATING: 1/10W; SOURCE: DIGI P1.0KJCT-ND; TOLERANCE: 5%
R529 R537 = 4.7K_OHM_1_10W_5%_0402: CCA: 69; MFG: PANASONIC; Part Number: ERJ-2GEJ472X
R533 = 10K_OHM_1_10W_5%_0402: CCA: 65; MFG: PANASONIC; Part Number: ERJ-2GEJ103X
U19 = SWITCH: CCA: 161; MFG: E-SWITCH; Part Number: TL1105F100Q; RATING: 12V
U21 = 74LVC1G07: IC, Non-Inverting Buffer, Open Drain; CCA: 147; MFG: TI; Part Number: SN74LVC1G07DBVR; SOURCE: DIGI 296-8485-1-ND
U502 = TS3A5018D: IC, Quad Switch; CCA: 172; MFG: TI; Part Number: TS3A5018DR; SOURCE: DIGI 296-17611-1-ND
U503 = Flash_N25Q_SPI_3_0.3V_32Mb_8SOW: IC, Flash; Part Number: MT25QL128ABA1ESE-0SIT
U505 = OSC: OSC, 100 MHz; CCA: 45; MFG: CTS-FREQUENCY CONTROLS; RATING: 50 PPM
U13 = 5AGXMA5GF31: IC, FPGA; MFG: ALTERA
U32 = DDP442x: IC, ASIC; CCA: 54; MFG: TI; Part Number: DLPC4420ZPC; SOURCE: PROVIDED BY TI
C92 C93 C846 C864 = CAP_NP: Capacitor; CCA: 114; MFG: KEMET; Part Number: C1206C107M9PACTU; RATING: 6.3V; SOURCE: DIGI 490-4539-1-ND; TOLERANCE: 20%; Type: X5R
C104 C109 C110 C850 C870 C874 C893 = CAP_NP: Capacitor; CCA: 112; MFG: MURATA; Part Number: GRM21BR71A106KE51L; RATING: 10V; SOURCE: DIGI 490-3905-1-ND; TOLERANCE: 10%; Type: X7R
C793 C794 C807-C813 C821 C829-C836 C838 C843-C845 C848 C849 C854 C857 C858 C861 C865 C866 C869 C871 C878 C879 C883 C884 C887 C888 C891 C894 C897 C898 C900 C903 C911-C914 C922-C932 C935 C938 C939 = CAP_NP: Capacitor; CCA: 34; MFG: KEMET; Part Number: C0402C104K8RACTU; RATING: 10V; SOURCE: DIGI 399-3520-1-ND; TOLERANCE: 10%; Type: X7R
R641 = R: Resistor; CCA: 142; MFG: YAGEO; Part Number: RC0402FR-071RL; RATING: 1/16W; SOURCE: DIGI 311-1.00LRCT-ND; TOLERANCE: 1%
R642 = R: Resistor; CCA: 61; MFG: PANASONIC; Part Number: ERJ-2BQJR36X; RATING: 1/8W; SOURCE: DIGI P.36AKCT-ND; TOLERANCE: 1%

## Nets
GND: C48.2 C57.2 C66.2 C92.2 C93.2 C104.2 C109.2 C110.2 C523.2 C524.2 C526.2 C529.2 C532.2 C543.2 C558.2 C559.2 C560.2 C561.2 C562.2 C564.2 C565.2 C569.2 C570.2 C571.2 C572.2 C574.2 C575.2 C576.2 C577.2 C587.2 C588.2 C589.2 C593.2 C594.2 C596.2 C597.2 C599.2 C600.2 C602.2 C605.2 C609.2 C610.2 C611.2 C614.2 C619.2 C625.2 C626.2 C628.2 C629.2 C643.2 C644.2 C647.2 C649.2 C655.2 C656.2 C659.2 C665.2 C674.2 C684.2 C688.2 C691.2 C697.2 C698.2 C702.2 C703.2 C705.2 C711.2 C720.2 C721.2 C727.2 C728.2 C729.2 C730.2 C731.2 C732.2 C733.2 C739.2 C741.2 C742.2 C743.2 C744.2 C745.2 C748.2 C754.2 C755.2 C761.2 C762.2 C763.2 C765.2 C766.2 C767.2 C774.2 C776.2 C781.2 C782.2 C783.2 C784.2 C793.2 C794.2 C807.2 C808.2 C809.2 C810.2 C811.2 C812.2 C813.2 C821.2 C829.2 C830.2 C831.2 C832.2 C833.2 C834.2 C835.2 C836.2 C838.2 C843.2 C844.2 C845.2 C846.2 C848.2 C849.2 C850.2 C854.2 C857.2 C858.2 C861.2 C864.2 C865.2 C866.2 C869.2 C870.2 C871.2 C874.2 C878.2 C879.2 C883.2 C884.2 C887.2 C888.2 C891.2 C893.2 C894.2 C897.2 C898.2 C900.2 C903.2 C911.2 C912.2 C913.2 C914.2 C922.2 C923.2 C924.2 C925.2 C926.2 C927.2 C928.2 C929.2 C930.2 C931.2 C932.2 C935.2 C938.2 C939.2 C966.2 J9.5 J9.6 J9.8 J9.10 J9.19 J9.24 J9.27 J9.30 J9.33 J9.36 J9.39 J9.42 J9.45 J9.48 J9.51 J9.52(GND) J9.53(GND) J9.54(GND) J9.55(GND) J19.1 J19.12 J21.2 J21.10 J23.A2 J23.A5 J23.A8 J23.A11 J23.A14 J23.B2 J23.B5 J23.B8 J23.B11 J24.1 J24.10 J25.1 J25.12 J32.1 J33.1 J54.6 J54.10 J54.11 J54.12 J55.6 J55.10 J55.11 J55.12 J56.7 MT1.1 MT2.1 MT3.1 MT4.1 Q4.S R89.1 R90.1 R91.1 R92.1 R509.2 R535.2 R538.1 R539.1 R541.1 R621.1 R745.2 R746.2 U5.3(GND) U13.E28(NCE) U13.F5(GND) U13.H26(GND) U13.M5(VCCR_GXBR) U13.M6(VCCL_GXBR1) U13.N6(VCCL_GXBR1) U13.N7(VCCH_GXBR1) U13.P5(VCCT_GXBR1) U13.P7(VCCA_GXBR1) U13.R6(VCCT_GXBR1) U13.R22(REFCLK2LP) U13.R23(REFCLK2LN) U13.T5(VCCR_GXBR) U13.T6(VCCR_GXBR) U13.T7(VCCH_GXBR0) U13.U6(VCCL_GXBR0) U13.V5(VCCT_GXBR0) U13.V7(VCCA_GXBR0) U13.W5(VCCR_GXBR) U13.W6(VCCR_GXBR) U13.W22(REFCLK0LP) U13.W23(REFCLK0LN) U19.3 U19.4 U21.1(~{OE}) U21.3(GND) U32.A1(GND) U32.A2(GND) U32.A3(GND) U32.A17(L_VDQPAD_1) U32.A18(L_VDQPAD_3) U32.A24(GND) U32.A25(GND) U32.A26(GND) U32.AA6(GND) U32.AA9(GND) U32.AA12(GND) U32.AA15(GND) U32.AA18(GND) U32.AA21(GND) U32.AB5(GND) U32.AB14(VTEST1) U32.AB15(VTEST2) U32.AB16(R_VDQPAD_3) U32.AB17(R_VDQPAD_1) U32.AB22(GND) U32.AC4(GND) U32.AC17(R_VDQPAD_6) U32.AC18(R_VDQPAD_4) U32.AC23(GND) U32.AD3(GND) U32.AD17(R_VDQPAD_2) U32.AD18(R_VDQPAD_0) U32.AD24(GND) U32.AE3(GND) U32.AE17(R_VDQPAD_7) U32.AE24(GND) U32.AE25(GND) U32.AF1(GND) U32.AF2(GND) U32.AF3(GND) U32.AF17(R_VDQPAD_5) U32.AF24(GND) U32.AF25(GND) U32.AF26(GND) U32.B1(GND) U32.B2(GND) U32.B3(GND) U32.B17(L_VDQPAD_5) U32.B18(L_VDQPAD_7) U32.B25(GND) U32.C3(GND) U32.C18(L_VDQPAD_2) U32.C24(GND) U32.D4(GND) U32.D17(L_VDQPAD_0) U32.D18(L_VDQPAD_6) U32.D23(GND) U32.E5(GND) U32.E15(VTEST3) U32.E16(VTEST4) U32.E17(L_VDQPAD_4) U32.E22(GND) U32.F6(GND) U32.F9(GND) U32.F12(GND) U32.F15(GND) U32.F18(GND) U32.F21(GND) U32.G5(GND) U32.J5(GND) U32.J6(GND) U32.J21(GND) U32.K5(LVDS_AVS1) U32.K26(PLLD_VAS) U32.L5(GND) U32.L12(GND) U32.L13(GND) U32.L14(GND) U32.L15(GND) U32.L23(PLLD_VSS) U32.L25(PLLM1_VAS) U32.M6(GND) U32.M11(GND) U32.M12(GND) U32.M13(GND) U32.M14(GND) U32.M15(GND) U32.M16(GND) U32.M21(GND) U32.M22(PLLM1_VSS) U32.N5(GND) U32.N11(GND) U32.N12(GND) U32.N13(GND) U32.N14(GND) U32.N15(GND) U32.N16(GND) U32.P11(GND) U32.P12(GND) U32.P13(GND) U32.P14(GND) U32.P15(GND) U32.P16(GND) U32.P24(PLLM2_VSS) U32.R5(GND) U32.R6(GND) U32.R11(GND) U32.R12(GND) U32.R13(GND) U32.R14(GND) U32.R15(GND) U32.R16(GND) U32.R24(PLLS_VAS) U32.R26(PLLM2_VAS) U32.T12(GND) U32.T13(GND) U32.T14(GND) U32.T15(GND) U32.U5(GND) U32.V5(LVDS_AVS2) U32.V6(GND) U32.V21(GND) U32.W5(GND) U32.Y5(GND) U502.8(GND) U502.15(EN) U503.4(VSS) U504.3(GND) U505.2(GND) U514.4(GND) Y1.2 Y1.4 ; also on sheet 2 5 6 7 8 9 10 11 12 13 14 15 16 17 18 19 20 21 22 23 24 25 26 27 35 36
P5V_M: J11.1 ; also on sheet 13 16 17 23 26
P12V: J54.1 J54.2 J55.1 J55.2 ; also on sheet 2 8 9 12 13 14 15 16 24 26
50MHZ_SSC: R747.2 U13.AG27(IO_3A)
A1P8V_S: R641.1 ; also on sheet 14
ACT_A_CLK: J54.5 U13.B6(IO_7A)
ACT_A_MISO: J54.4 U13.A5(IO_7A)
ACT_A_MOSI: J54.3 U13.A6(IO_7A)
ACT_B_CLK: J54.9 U13.E6(IO_7A)
ACT_B_MISO: J54.8 U13.D6(IO_7A)
ACT_B_MOSI: J54.7 U13.D5(IO_7A)
ACT_C_CLK: J55.5 U13.K6(IO_7A)
ACT_C_MISO: J55.4 U13.H6(IO_7A)
ACT_C_MOSI: J55.3 U13.G7(IO_7A)
ACT_D_CLK: J55.9 U13.K8(IO_7B)
ACT_D_MISO: J55.8 U13.J10(IO_7B)
ACT_D_MOSI: J55.7 U13.K7(IO_7A)
ACT_GPIO_0: J56.1 U13.K10(IO_7B)
ACT_GPIO_1: J56.2 U13.AC18(IO_4D)
ACT_SYNC_0: TP18.1 U13.AK4(IO_4A) ; also on sheet 25
ACT_SYNC_1: TP19.1 U13.AK5(IO_4A) ; also on sheet 25
CFLSH_HOLD: R529.2 U503.7(HOLD#)
CFLSH_W: R537.2 U503.3(W#/Vpp)
DDR3_0_A0: U13.AK10(IO_4B) ; also on sheet 5
DDR3_0_A1: U13.AK11(IO_4B) ; also on sheet 5
DDR3_0_A2: U13.AJ10(IO_4B) ; also on sheet 5
DDR3_0_A3: U13.AH9(IO_4B) ; also on sheet 5
DDR3_0_A4: U13.AG10(IO_4B) ; also on sheet 5
DDR3_0_A5: U13.AF10(IO_4B) ; also on sheet 5
DDR3_0_A6: U13.AE11(IO_4B) ; also on sheet 5
DDR3_0_A7: U13.AJ12(IO_4C) ; also on sheet 5
DDR3_0_A8: U13.AD13(IO_4C) ; also on sheet 5
DDR3_0_A9: U13.AC15(IO_4D) ; also on sheet 5
DDR3_0_A10: U13.AC13(IO_4C) ; also on sheet 5
DDR3_0_A11: U13.AB13(IO_4C) ; also on sheet 5
DDR3_0_A12: U13.AA13(IO_4C) ; also on sheet 5
DDR3_0_A13: U13.AE15(IO_4C) ; also on sheet 5
DDR3_0_BA0: U13.AB14(IO_4C) ; also on sheet 5
DDR3_0_BA1: U13.AA14(IO_4C) ; also on sheet 5
DDR3_0_BA2: U13.Y13(IO_4C) ; also on sheet 5
DDR3_0_CASZ: U13.AB17(IO_4D) ; also on sheet 5
DDR3_0_CKE: U13.AG14(IO_4C) ; also on sheet 5
DDR3_0_CLK_N: U13.AA15(IO_4D) ; also on sheet 5
DDR3_0_CLK_P: U13.AB15(IO_4D) ; also on sheet 5
DDR3_0_DQ0: U13.AK12(IO_4C) ; also on sheet 5
DDR3_0_DQ1: U13.AH11(IO_4C) ; also on sheet 5
DDR3_0_DQ2: U13.AG11(IO_4C) ; also on sheet 5
DDR3_0_DQ3: U13.AF12(IO_4C) ; also on sheet 5
DDR3_0_DQ4: U13.AF13(IO_4C) ; also on sheet 5
DDR3_0_DQ5: U13.AD12(IO_4C) ; also on sheet 5
DDR3_0_DQ6: U13.AC12(IO_4C) ; also on sheet 5
DDR3_0_DQ7: U13.AB12(IO_4C) ; also on sheet 5
DDR3_0_DQ8: U13.AJ13(IO_4C) ; also on sheet 5
DDR3_0_DQ9: U13.AH13(IO_4C) ; also on sheet 5
DDR3_0_DQ10: U13.AH14(IO_4C) ; also on sheet 5
DDR3_0_DQ11: U13.AH15(IO_4C) ; also on sheet 5
DDR3_0_DQ12: U13.AG15(IO_4C) ; also on sheet 5
DDR3_0_DQ13: U13.AF15(IO_4C) ; also on sheet 5
DDR3_0_DQ14: U13.AE13(IO_4C) ; also on sheet 5
DDR3_0_DQ15: U13.AE14(IO_4C) ; also on sheet 5
DDR3_0_DQ16: U13.AK16(IO_4D) ; also on sheet 5
DDR3_0_DQ17: U13.AJ16(IO_4D) ; also on sheet 5
DDR3_0_DQ18: U13.AH17(IO_4D) ; also on sheet 5
DDR3_0_DQ19: U13.AG16(IO_4D) ; also on sheet 5
DDR3_0_DQ20: U13.AG17(IO_4D) ; also on sheet 5
DDR3_0_DQ21: U13.AD15(IO_4D) ; also on sheet 5
DDR3_0_DQ22: U13.AD16(IO_4D) ; also on sheet 5
DDR3_0_DQ23: U13.AB16(IO_4D) ; also on sheet 5
DDR3_0_DQ24: U13.AK19(IO_4D) ; also on sheet 5
DDR3_0_DQ25: U13.AG19(IO_4D) ; also on sheet 5
DDR3_0_DQ26: U13.AF19(IO_4D) ; also on sheet 5
DDR3_0_DQ27: U13.AF18(IO_4D) ; also on sheet 5
DDR3_0_DQ28: U13.AE17(IO_4D) ; also on sheet 5
DDR3_0_DQ29: U13.AE18(IO_4D) ; also on sheet 5
DDR3_0_DQ30: U13.AD18(IO_4D) ; also on sheet 5
DDR3_0_DQ31: U13.AB18(IO_4D) ; also on sheet 5
DDR3_0_LDQS0_N: U13.AG12(IO_4C) ; also on sheet 5
DDR3_0_LDQS0_P: U13.AH12(IO_4C) ; also on sheet 5
DDR3_0_LDQS1_N: U13.AJ18(IO_4D) ; also on sheet 5
DDR3_0_LDQS1_P: U13.AK17(IO_4D) ; also on sheet 5
DDR3_0_NCS: U13.AF16(IO_4D) ; also on sheet 5
DDR3_0_ODT: U13.AC16(IO_4D) ; also on sheet 5
DDR3_0_RASZ: U13.AA18(IO_4D) ; also on sheet 5
DDR3_0_RESETZ: U13.AJ19(IO_4D) ; also on sheet 5
DDR3_0_UDQS0_N: U13.AJ15(IO_4C) ; also on sheet 5
DDR3_0_UDQS0_P: U13.AK14(IO_4C) ; also on sheet 5
DDR3_0_UDQS1_N: U13.AH19(IO_4D) ; also on sheet 5
DDR3_0_UDQS1_P: U13.AH18(IO_4D) ; also on sheet 5
DDR3_0_WEZ: U13.AA17(IO_4D) ; also on sheet 5
DDR3_1_A0: U13.A11(IO_7B) ; also on sheet 6
DDR3_1_A1: U13.K17(IO_7D) ; also on sheet 6
DDR3_1_A2: U13.J16(IO_7D) ; also on sheet 6
DDR3_1_A3: U13.G17(IO_7D) ; also on sheet 6
DDR3_1_A4: U13.E19(IO_7D) ; also on sheet 6
DDR3_1_A5: U13.H18(IO_7D) ; also on sheet 6
DDR3_1_A6: U13.B13(IO_7C) ; also on sheet 6
DDR3_1_A7: U13.B12(IO_7C) ; also on sheet 6
DDR3_1_A8: U13.E12(IO_7C) ; also on sheet 6
DDR3_1_A9: U13.F13(IO_7C) ; also on sheet 6
DDR3_1_A10: U13.G14(IO_7C) ; also on sheet 6
DDR3_1_A11: U13.G11(IO_7C) ; also on sheet 6
DDR3_1_A12: U13.H13(IO_7C) ; also on sheet 6
DDR3_1_A13: U13.H12(IO_7C) ; also on sheet 6
DDR3_1_BA0: U13.J13(IO_7C) ; also on sheet 6
DDR3_1_BA1: U13.K14(IO_7C) ; also on sheet 6
DDR3_1_BA2: U13.K16(IO_7D) ; also on sheet 6
DDR3_1_CASZ: U13.J17(IO_7D) ; also on sheet 6
DDR3_1_CKE: U13.C5(IO_7A) ; also on sheet 6
DDR3_1_CLK_N: U13.H10(IO_7B) ; also on sheet 6
DDR3_1_CLK_P: U13.G10(IO_7B) ; also on sheet 6
DDR3_1_DQ0: U13.E13(IO_7C) ; also on sheet 6
DDR3_1_DQ1: U13.G12(IO_7C) ; also on sheet 6
DDR3_1_DQ2: U13.D13(IO_7C) ; also on sheet 6
DDR3_1_DQ3: U13.K11(IO_7C) ; also on sheet 6
DDR3_1_DQ4: U13.D12(IO_7C) ; also on sheet 6
DDR3_1_DQ5: U13.J11(IO_7C) ; also on sheet 6
DDR3_1_DQ6: U13.C13(IO_7C) ; also on sheet 6
DDR3_1_DQ7: U13.F11(IO_7C) ; also on sheet 6
DDR3_1_DQ8: U13.A15(IO_7C) ; also on sheet 6
DDR3_1_DQ9: U13.A14(IO_7C) ; also on sheet 6
DDR3_1_DQ10: U13.A13(IO_7C) ; also on sheet 6
DDR3_1_DQ11: U13.B15(IO_7C) ; also on sheet 6
DDR3_1_DQ12: U13.D15(IO_7C) ; also on sheet 6
DDR3_1_DQ13: U13.F14(IO_7C) ; also on sheet 6
DDR3_1_DQ14: U13.G13(IO_7C) ; also on sheet 6
DDR3_1_DQ15: U13.J14(IO_7C) ; also on sheet 6
DDR3_1_DQ16: U13.A17(IO_7D) ; also on sheet 6
DDR3_1_DQ17: U13.A16(IO_7D) ; also on sheet 6
DDR3_1_DQ18: U13.C17(IO_7D) ; also on sheet 6
DDR3_1_DQ19: U13.D16(IO_7D) ; also on sheet 6
DDR3_1_DQ20: U13.F15(IO_7D) ; also on sheet 6
DDR3_1_DQ21: U13.G16(IO_7D) ; also on sheet 6
DDR3_1_DQ22: U13.G15(IO_7D) ; also on sheet 6
DDR3_1_DQ23: U13.H15(IO_7D) ; also on sheet 6
DDR3_1_DQ24: U13.A19(IO_7D) ; also on sheet 6
DDR3_1_DQ25: U13.B19(IO_7D) ; also on sheet 6
DDR3_1_DQ26: U13.D19(IO_7D) ; also on sheet 6
DDR3_1_DQ27: U13.D18(IO_7D) ; also on sheet 6
DDR3_1_DQ28: U13.E18(IO_7D) ; also on sheet 6
DDR3_1_DQ29: U13.F17(IO_7D) ; also on sheet 6
DDR3_1_DQ30: U13.G18(IO_7D) ; also on sheet 6
DDR3_1_DQ31: U13.J18(IO_7D) ; also on sheet 6
DDR3_1_LDQS0_N: U13.K12(IO_7C) ; also on sheet 6
DDR3_1_LDQS0_P: U13.J12(IO_7C) ; also on sheet 6
DDR3_1_LDQS1_N: U13.C16(IO_7D) ; also on sheet 6
DDR3_1_LDQS1_P: U13.B16(IO_7D) ; also on sheet 6
DDR3_1_NCS: U13.E16(IO_7D) ; also on sheet 6
DDR3_1_ODT: U13.J15(IO_7D) ; also on sheet 6
DDR3_1_RASZ: U13.H16(IO_7D) ; also on sheet 6
DDR3_1_RESETZ: U13.A10(IO_7B) ; also on sheet 6
DDR3_1_UDQS0_N: U13.D14(IO_7C) ; also on sheet 6
DDR3_1_UDQS0_P: U13.C14(IO_7C) ; also on sheet 6
DDR3_1_UDQS1_N: U13.C19(IO_7D) ; also on sheet 6
DDR3_1_UDQS1_P: U13.B18(IO_7D) ; also on sheet 6
DDR3_1_WEZ: U13.E15(IO_7C) ; also on sheet 6
DDR_VREF: C647.1 C656.1 C698.1 C702.1 U13.AD14(VREFB4CN0) U13.AD17(VREFB4DN0) U13.K13(VREFB7CN0) U13.K18(VREFB7DN0) ; also on sheet 5 6 9
EXT_ARSTZ: U21.2(I) ; also on sheet 2 12 16
F_CONF_DONE: R79.1 R88.1 U13.B30(CONF_DONE)
F_CSZ: R533.2 U13.AA25(NCSO_3A_AA25/DATA4) U502.3(NO1)
F_DATA0: U13.AK28(AS_DATA0,ASDO_3A_AK28/DATA0) U502.6(NO2)
F_DATA1: U13.AK29(AS_DATA1_3A_AK29/DATA1) U502.10(NO3)
F_DCLK: U13.AJ29(DCLK) U502.13(NO4)
F_NCONFIG: R542.1 U13.E27(NCONFIG)
F_NSTATUS: R543.1 U13.D28(NSTATUS)
F_TCK: J21.1 R535.1 U13.AG29(TCK)
F_TDI: J21.9 R524.2 U13.AF29(TDI)
F_TDO: J21.3 U13.AF30(TDO)
F_TMS: J21.5 R528.2 U13.AG30(TMS)
FE_5V: J9.1 J9.2 J9.3 J9.4 J11.2
FE_RSTZ: J9.22 R509.1 U5.2(I)
FE_SPR1: J9.13 TP501.1
FPGA_CK: U502.12(COM4) U503.6(CK)
FPGA_CLK: U13.C28(CLK) U505.3(OUT)
FPGA_CSZ: U502.4(COM1) U503.1(CS#)
FPGA_RSTZ: R109.2 U13.AF4(IO_4A) U19.1 U19.2 U21.4(O)
FPGA_SI: U502.7(COM2) U503.5(SI/DQ0)
FPGA_SO: U502.9(COM3) U503.2(SO/DQ1)
HTPDN: D2.1(CATHODE) J9.25 U13.AE7(IO_4A)
I2C_BUSY: J9.17 R23.2 ; also on sheet 17
LOCKN: D1.1(CATHODE) J9.26 U13.AD7(IO_4A)
M_FIELD: U13.AK6(IO_4A) ; also on sheet 34
M_P1_A0: U13.AH23(IO_3D) ; also on sheet 34
M_P1_A1: U13.AG23(IO_3D) ; also on sheet 34
M_P1_A2: U13.AG24(IO_3A) ; also on sheet 34
M_P1_A3: U13.AF24(IO_3A) ; also on sheet 34
M_P1_A4: U13.AE23(IO_3A) ; also on sheet 34
M_P1_A5: U13.AD23(IO_3A) ; also on sheet 34
M_P1_A6: U13.AD24(IO_3A) ; also on sheet 34
M_P1_A7: U13.AC24(IO_3A) ; also on sheet 34
M_P1_A8: U13.AB23(IO_3A) ; also on sheet 34
M_P1_A9: U13.AB24(IO_3A) ; also on sheet 34
M_P1_B0: U13.AK24(IO_3A) ; also on sheet 34
M_P1_B1: U13.AJ24(IO_3A) ; also on sheet 34
M_P1_B2: U13.AJ25(IO_3A) ; also on sheet 34
M_P1_B3: U13.AH25(IO_3A) ; also on sheet 34
M_P1_B4: U13.AG25(IO_3A) ; also on sheet 34
M_P1_B5: U13.AF25(IO_3A) ; also on sheet 34
M_P1_B6: U13.AE25(IO_3A) ; also on sheet 34
M_P1_B7: U13.AD25(IO_3A) ; also on sheet 34
M_P1_B8: U13.AC25(IO_3A) ; also on sheet 34
M_P1_B9: U13.AB25(IO_3A) ; also on sheet 34
M_P1_C0: U13.AK25(IO_3A) ; also on sheet 34
M_P1_C1: U13.AK26(IO_3A) ; also on sheet 34
M_P1_C2: U13.AH26(IO_3A) ; also on sheet 34
M_P1_C3: U13.AG26(IO_3A) ; also on sheet 34
M_P1_C4: U13.AE26(IO_3A) ; also on sheet 34
M_P1_C5: U13.AK27(IO_3A) ; also on sheet 34
M_P1_C6: U13.AJ27(IO_3A) ; also on sheet 34
M_P1_C7: U13.AH28(IO_3A) ; also on sheet 34
M_P1_C8: U13.AF27(IO_3A) ; also on sheet 34
M_P1_C9: U13.AE27(IO_3A) ; also on sheet 34
M_P1_HSYNC: U13.AG28(IO_3A) ; also on sheet 34
M_P1_VSYNC: U13.AJ6(IO_4A) ; also on sheet 34
M_P2_A0: U13.AG20(IO_3D) ; also on sheet 34
M_P2_A1: U13.AE20(IO_3D) ; also on sheet 34
M_P2_A2: U13.AD19(IO_3D) ; also on sheet 34
M_P2_A3: U13.AD20(IO_3D) ; also on sheet 34
M_P2_A4: U13.AC19(IO_3D) ; also on sheet 34
M_P2_A5: U13.AB19(IO_3D) ; also on sheet 34
M_P2_A6: U13.AB20(IO_3D) ; also on sheet 34
M_P2_A7: U13.AA19(IO_3D) ; also on sheet 34
M_P2_A8: U13.AA20(IO_3D) ; also on sheet 34
M_P2_A9: U13.Y20(IO_3D) ; also on sheet 34
M_P2_B0: U13.AK20(IO_3D) ; also on sheet 34
M_P2_B1: U13.AK21(IO_3D) ; also on sheet 34
M_P2_B2: U13.AJ21(IO_3D) ; also on sheet 34
M_P2_B3: U13.AH20(IO_3D) ; also on sheet 34
M_P2_B4: U13.AG21(IO_3D) ; also on sheet 34
M_P2_B5: U13.AF21(IO_3D) ; also on sheet 34
M_P2_B6: U13.AD21(IO_3D) ; also on sheet 34
M_P2_B7: U13.AC21(IO_3D) ; also on sheet 34
M_P2_B8: U13.AB21(IO_3D) ; also on sheet 34
M_P2_B9: U13.AA21(IO_3D) ; also on sheet 34
M_P2_C0: U13.AK22(IO_3D) ; also on sheet 34
M_P2_C1: U13.AJ22(IO_3D) ; also on sheet 34
M_P2_C2: U13.AH22(IO_3D) ; also on sheet 34
M_P2_C3: U13.AG22(IO_3D) ; also on sheet 34
M_P2_C4: U13.AF22(IO_3D) ; also on sheet 34
M_P2_C5: U13.AE22(IO_3D) ; also on sheet 34
M_P2_C6: U13.AD22(IO_3D) ; also on sheet 34
M_P2_C7: U13.AC22(IO_3D) ; also on sheet 34
M_P2_C8: U13.AB22(IO_3D) ; also on sheet 34
M_P2_C9: U13.AA22(IO_3D) ; also on sheet 34
M_P_CLK1: U13.AJ28(IO_3A) ; also on sheet 34
M_P_DATAEN1: U13.AF28(IO_3A) ; also on sheet 34
MSEL0: R85.1 R90.2 U13.C30(MSEL0)
MSEL1: R87.1 R92.2 U13.D30(MSEL1)
MSEL2: R84.1 R89.2 U13.C29(MSEL2)
MSEL3: R86.1 R91.2 U13.D29(MSEL3)
MSEL4: R540.1 R541.2 U13.F26(MSEL4)
P1P1V_S: C110.1 C829.1 C831.1 C833.1 C835.1 C838.1 C843.1 C846.1 C849.1 C854.1 C861.1 C865.1 C866.1 C869.1 C879.1 C883.1 C884.1 C887.1 C893.1 C894.1 C897.1 C903.1 C911.1 C913.1 C914.1 C928.1 C931.1 R642.1 U32.AA8(VDDC) U32.AA11(VDDC) U32.AA14(VDDC) U32.AA17(VDDC) U32.AA20(VDDC) U32.F7(VDDC) U32.F10(VDDC) U32.F13(VDDC) U32.F16(VDDC) U32.F19(VDDC) U32.G21(VDDC) U32.H6(VDDC) U32.K21(VDDC) U32.L6(VDDC) U32.L11(VDDC) U32.L16(VDDC) U32.N21(VDDC) U32.P6(VDDC) U32.T11(VDDC) U32.T16(VDDC) U32.T21(VDDC) U32.U6(VDDC) U32.W21(VDDC) U32.Y6(VDDC) ; also on sheet 14
P1P5V: C57.1 C644.1 C649.1 C655.1 C659.1 C674.1 C684.1 C688.1 C697.1 C703.1 C711.1 C720.1 C721.1 C727.1 C728.1 C729.1 C732.1 C741.1 C742.1 C743.1 C744.1 C745.1 C754.1 C765.1 C766.1 U13.A9(VCCIO7B) U13.A12(VCCIO7C) U13.A18(VCCIO7D) U13.AE10(VCCIO4B) U13.AE12(VCCIO4C) U13.AE16(VCCIO4D) U13.AG9(VCCIO4B) U13.AG13(VCCIO4C) U13.AG18(VCCIO4D) U13.AH10(VCCIO4B) U13.AH16(VCCIO4D) U13.AK9(VCCIO4B) U13.AK13(VCCIO4C) U13.AK15(VCCIO4C) U13.AK18(VCCIO4D) U13.C3(VCCIO7A) U13.C6(VCCIO7A) U13.C9(VCCIO7B) U13.C12(VCCIO7C) U13.C15(VCCIO7C) U13.C18(VCCIO7D) U13.D7(VCCIO7B) U13.F2(VCCIO7A) U13.F6(VCCIO7A) U13.F9(VCCIO7B) U13.F12(VCCIO7C) U13.F16(VCCIO7D) U13.F18(VCCIO7D) ; also on sheet 5 6 8 9 25
P1P5V_FIL: C691.1 C733.1 U13.N25(VCCH_GXBL1) U13.T24(VCCH_GXBL0) ; also on sheet 7 9
P1P8V_S: C109.1 C830.1 C834.1 C845.1 C850.1 C864.1 C871.1 C878.1 C912.1 C922.1 C923.1 C924.1 C925.1 C926.1 C927.1 C929.1 C930.1 C932.1 C935.1 C938.1 C939.1 U32.AA5(LVDSAVD) U32.AA13(DRAMVDD) U32.AE1(LVDSAVD) U32.C1(LVDSAVD) U32.F5(LVDSAVD) U32.F14(DRAMVDD) U32.G6(LVDSAVD) U32.H5(DRAMVDD) U32.H21(DRAMVDD) U32.K6(LVDSAVD) U32.M5(LVDSAVD) U32.N6(DRAMVDD) U32.P5(LVDSAVD) U32.P21(DRAMVDD) U32.T5(LVDSAVD) U32.T6(DRAMVDD) U32.U21(DRAMVDD) U32.W6(LVDSAVD) ; also on sheet 14
P1P15V: C529.1 C543.1 C560.1 C561.1 C562.1 C565.1 C571.1 C574.1 C575.1 C577.1 U13.M25(VCCL_GXBL1) U13.M26(VCCR_GXBL) U13.R25(VCCR_GXBL) U13.R26(VCCR_GXBL) U13.T25(VCCL_GXBL0) U13.T26(VCCL_GXBL0) U13.W25(VCCR_GXBL) U13.W26(VCCR_GXBL) ; also on sheet 8
P1P15V_FIL: C558.1 C564.1 C572.1 U13.P26(VCCT_GXBL1) U13.U25(VCCT_GXBL0) U13.V26(VCCT_GXBL0) ; also on sheet 8
P2P5V: C665.1 C705.1 C730.1 C731.1 C739.1 C774.1 U13.L8(VCCPD7A) U13.L13(VCCPD7BCD) U13.L17(VCCPD7BCD) U13.M9(VCCPD7BCD) U13.Y10(VCCPD4BCD) U13.Y15(VCCPD4BCD) U13.Y18(VCCPD4BCD) ; also on sheet 7 9
P2P5V_FIL: C609.1 C643.1 U13.P24(VCCA_GXBL1) U13.V24(VCCA_GXBL0) ; also on sheet 7 9
P3P3V: C48.1 C66.1 C523.1 C526.1 C559.1 C569.1 C570.1 C576.1 C587.1 C588.1 C589.1 C593.1 C594.1 C596.1 C597.1 C599.1 C600.1 C602.1 C605.1 C610.1 C611.1 C614.1 C619.1 C625.1 C626.1 C628.1 C629.1 C748.1 C755.1 C761.1 C762.1 C763.1 C767.1 C776.1 C781.1 C782.1 C783.1 C784.1 C966.1 FB500.1 FB501.1 J21.4 R82.2 R84.2 R85.2 R86.2 R87.2 R88.2 R109.1 R120.2 R121.2 R510.1 R511.1 R524.1 R528.1 R529.1 R532.1 R533.1 R537.1 R540.2 R542.2 R543.2 U13.A20(VCCIO8D) U13.A22(VCCIO8D) U13.A25(VCCIO8A) U13.AA7(VCCPD4A) U13.AA23(VCCPD3) U13.AB5(VCCIO4A) U13.AD5(VCCIO4A) U13.AD26(VCCIO3A) U13.AE19(VCCIO3D) U13.AE21(VCCIO3D) U13.AE24(VCCIO3A) U13.AH3(VCCIO4A) U13.AH6(VCCIO4A) U13.AH21(VCCIO3D) U13.AH24(VCCIO3A) U13.AH27(VCCIO3A) U13.AK23(VCCIO3D) U13.C21(VCCIO8D) U13.C24(VCCIO8A) U13.F22(VCCIO8D) U13.F24(VCCIO8A) U13.L23(VCCIO8A) U13.M22(VCCPD8) U13.M23(VCCPD8) U13.Y21(VCCPD3) U21.5(VCC) U502.16(VCC) U503.8(VCC) U514.5(FS) U514.7(VDD) ; also on sheet 7 9 25
P3P3V_M: R23.1 U5.5(VCC) ; also on sheet 12 13 14 15 16 17 18 20 21 23 24 27 35
P3P3V_S: C104.1 C821.1 C832.1 C836.1 C844.1 C848.1 C857.1 C858.1 C870.1 C874.1 C888.1 C891.1 C898.1 C900.1 U32.AA7(VDD33) U32.AA10(VDD33) U32.AA16(VDD33) U32.AA19(VDD33) U32.AE26(CFO_VDD33) U32.F8(VDD33) U32.F11(VDD33) U32.F17(VDD33) U32.F20(VDD33) U32.L21(VDD33) U32.R21(VDD33) U32.Y21(VDD33) ; also on sheet 12 14 15 19 22 25 26
PLLD_VAD_S: C809.1 FB510.2 U32.K25(PLLD_VAD)
PLLD_VDD_S: C810.1 FB511.2 U32.L22(PLLD_VDD)
PLLM1_VAD_S: C808.1 FB513.2 U32.L24(PLLM1_VAD)
PLLM1_VDD_S: C807.1 FB512.2 U32.L26(PLLM1_VDD)
PLLM2_VAD_S: C812.1 FB515.2 U32.R25(PLLM2_VAD)
PLLM2_VDD_S: C813.1 FB516.2 U32.P23(PLLM2_VDD)
PLLS_VAD_S: C811.1 FB514.2 U32.R23(PLLS_VAD)
PROG_FLASH_IN: R531.1 ; also on sheet 35
PWRGOOD: U5.4(O) ; also on sheet 12 18 21
RFU_15_H7: J19.11 J23.A15 U13.H7(IO_7A)
RFU_15_J6: J19.10 J23.A13 U13.J6(IO_7A)
RX0N: C44.2 J9.28
RX0P: C43.2 J9.29
RX1N: C42.2 J9.31
RX1P: C41.2 J9.32
RX2N: C40.2 J9.34
RX2P: C39.2 J9.35
RX3N: C38.2 J9.37
RX3P: C37.2 J9.38
RX4N: C36.2 J9.40
RX4P: C35.2 J9.41
RX5N: C34.2 J9.43
RX5P: C33.2 J9.44
RX6N: C32.2 J9.46
RX6P: C31.2 J9.47
RX7N: C30.2 J9.49
RX7P: C29.2 J9.50
S_FIELD: U13.AA6(IO_4A) ; also on sheet 34
S_P1_A0: U13.E24(IO_8A) ; also on sheet 34
S_P1_A1: U13.F23(IO_8D) ; also on sheet 34
S_P1_A2: U13.G23(IO_8D) ; also on sheet 34
S_P1_A3: U13.G24(IO_8A) ; also on sheet 34
S_P1_A4: U13.H24(IO_8A) ; also on sheet 34
S_P1_A5: U13.J24(IO_8A) ; also on sheet 34
S_P1_A6: U13.J23(IO_8A) ; also on sheet 34
S_P1_A7: U13.K24(IO_8A) ; also on sheet 34
S_P1_A8: U13.K23(IO_8A) ; also on sheet 34
S_P1_A9: U13.L22(IO_8A) ; also on sheet 34
S_P1_B0: U13.A24(IO_8A) ; also on sheet 34
S_P1_B1: U13.A23(IO_8A) ; also on sheet 34
S_P1_B2: U13.B24(IO_8A) ; also on sheet 34
S_P1_B3: U13.D24(IO_8A) ; also on sheet 34
S_P1_B4: U13.E25(IO_8A) ; also on sheet 34
S_P1_B5: U13.F25(IO_8A) ; also on sheet 34
S_P1_B6: U13.G25(IO_8A) ; also on sheet 34
S_P1_B7: U13.H25(IO_8A) ; also on sheet 34
S_P1_B8: U13.J25(IO_8A) ; also on sheet 34
S_P1_B9: U13.K25(IO_8A) ; also on sheet 34
S_P1_C0: U13.B25(IO_8A) ; also on sheet 34
S_P1_C1: U13.C25(IO_8A) ; also on sheet 34
S_P1_C2: U13.D25(IO_8A) ; also on sheet 34
S_P1_C3: U13.A26(IO_8A) ; also on sheet 34
S_P1_C4: U13.A27(IO_8A) ; also on sheet 34
S_P1_C5: U13.B27(IO_8A) ; also on sheet 34
S_P1_C6: U13.C27(IO_8A) ; also on sheet 34
S_P1_C7: U13.C26(IO_8A) ; also on sheet 34
S_P1_C8: U13.D26(IO_8A) ; also on sheet 34
S_P1_C9: U13.D27(IO_8A) ; also on sheet 34
S_P1_HSYNC: U13.B28(IO_8A) ; also on sheet 34
S_P1_VSYNC: U13.AA8(IO_4A) ; also on sheet 34
S_P2_A0: U13.C20(IO_8D) ; also on sheet 34
S_P2_A1: U13.D20(IO_8D) ; also on sheet 34
S_P2_A2: U13.F20(IO_8D) ; also on sheet 34
S_P2_A3: U13.F19(IO_8D) ; also on sheet 34
S_P2_A4: U13.G20(IO_8D) ; also on sheet 34
S_P2_A5: U13.G19(IO_8D) ; also on sheet 34
S_P2_A6: U13.H19(IO_8D) ; also on sheet 34
S_P2_A7: U13.J20(IO_8D) ; also on sheet 34
S_P2_A8: U13.J19(IO_8D) ; also on sheet 34
S_P2_A9: U13.K19(IO_8D) ; also on sheet 34
S_P2_B0: U13.A21(IO_8D) ; also on sheet 34
S_P2_B1: U13.B21(IO_8D) ; also on sheet 34
S_P2_B2: U13.D21(IO_8D) ; also on sheet 34
S_P2_B3: U13.E21(IO_8D) ; also on sheet 34
S_P2_B4: U13.F21(IO_8D) ; also on sheet 34
S_P2_B5: U13.G21(IO_8D) ; also on sheet 34
S_P2_B6: U13.H21(IO_8D) ; also on sheet 34
S_P2_B7: U13.J21(IO_8D) ; also on sheet 34
S_P2_B8: U13.K21(IO_8D) ; also on sheet 34
S_P2_B9: U13.K20(IO_8D) ; also on sheet 34
S_P2_C0: U13.B22(IO_8D) ; also on sheet 34
S_P2_C1: U13.C23(IO_8D) ; also on sheet 34
S_P2_C2: U13.C22(IO_8D) ; also on sheet 34
S_P2_C3: U13.D23(IO_8D) ; also on sheet 34
S_P2_C4: U13.D22(IO_8D) ; also on sheet 34
S_P2_C5: U13.E22(IO_8D) ; also on sheet 34
S_P2_C6: U13.G22(IO_8D) ; also on sheet 34
S_P2_C7: U13.H22(IO_8D) ; also on sheet 34
S_P2_C8: U13.J22(IO_8D) ; also on sheet 34
S_P2_C9: U13.K22(IO_8D) ; also on sheet 34
S_P_CLK1: U13.A29(IO_8A) ; also on sheet 34
S_P_DATAEN1: U13.A28(IO_8A) ; also on sheet 34
SCL0: J9.18 ; also on sheet 17 35
SCL1: J9.14 R191.1 ; also on sheet 16 17 25 35
SCL2: R192.1 ; also on sheet 17
SDA0: J9.20 ; also on sheet 17 35
SDA1: J9.16 R190.1 ; also on sheet 16 17 25 35
SDA2: R193.1 ; also on sheet 17
SSP1_CLK: J56.5 U502.14(NC4) ; also on sheet 35
SSP1_CSZ_0: U502.2(NC1) ; also on sheet 35
SSP1_CSZ_1: J56.3 ; also on sheet 35
SSP1_DI: J56.6 U502.11(NC3) ; also on sheet 35
SSP1_DO: J56.4 U502.5(NC2) ; also on sheet 35
SWAP_ORDER: J33.2 R121.1 U13.AB7(IO_4A)
SWAP_PN: J32.2 R120.1 U13.AB6(IO_4A)
TEST_4A_AF7: J25.9 U13.AF7(IO_4A) ; also on sheet 25
TEST_4B_AD8: J25.8 U13.AD8(IO_4B) ; also on sheet 25
TEST_4C_Y12: J25.7 U13.Y12(IO_4C)
TEST_4D_AA16: J25.6 U13.AA16(IO_4D)
TEST_7A_A4: J25.5 U13.A4(IO_7A)
TEST_7A_G6: J25.4 U13.G6(IO_7A)
TEST_7B_F10: J25.3 U13.F10(IO_7B)
TEST_7D_D17: J25.2 U13.D17(IO_7D)
TEST_MUX_0: J19.2 J23.A1 U13.AD10(IO_4B)
TEST_MUX_1: J19.3 J23.A3 U13.AD11(IO_4B)
TEST_MUX_2: J23.B1 J24.9 U13.AB9(IO_4B)
TEST_MUX_3: J23.B3 J24.8 U13.AB10(IO_4B)
TEST_MUX_4: J19.4 J23.A4 U13.AB11(IO_4B)
TEST_MUX_5: J19.5 J23.A6 U13.AA10(IO_4B)
TEST_MUX_6: J23.B4 J24.7 U13.AA11(IO_4B)
TEST_MUX_7: J23.B6 J24.6 U13.AA12(IO_4B)
TEST_MUX_8: J19.6 J23.A7 U13.B10(IO_7B)
TEST_MUX_9: J19.7 J23.A9 U13.C11(IO_7B)
TEST_MUX_10: J23.B7 J24.5 U13.C10(IO_7B)
TEST_MUX_11: J23.B9 J24.4 U13.D11(IO_7B)
TEST_MUX_12: J19.8 J23.A10 U13.D10(IO_7B)
TEST_MUX_13: J19.9 J23.A12 U13.D9(IO_7B)
TEST_MUX_14: J23.B10 J24.3 U13.E10(IO_7B)
TEST_MUX_15: J23.B12 J24.2 U13.E9(IO_7B)
TEST_RX8_N: C545.1 U13.H29(GXB_RX_L8N)
TEST_RX8_P: C549.1 U13.H30(GXB_RX_L8P)
Test_TX8_N: C545.2 U13.G27(GXB_TX_L8N)
Test_TX8_P: C549.2 U13.G28(GXB_TX_L8P)
VBY1_CLK_N: C547.2 U504.5(OUTz)
VBY1_CLK_P: C546.2 U504.4(OUT)
VX1_3D_EN: J9.15 J25.11 U13.AC6(IO_4A)
VX1_LR_SYNC: J9.21 J25.10 U13.AE6(IO_4A)
N18066834: C92.1 C794.1 FB511.1 FB512.1 FB514.1 FB516.1 R642.2
N18068184: C93.1 C793.1 FB510.1 FB513.1 FB515.1 R641.2
N18660551: Q4.G R79.2
N18683881: D1.2(ANODE) R511.2
N18683884: D2.2(ANODE) R510.2
N18684016: R621.2 U13.E4(RZQ_5)
N18770466: C532.1 FB501.2 U505.1(EN) U505.4(VCC)
N18855184: R531.2 R532.2 U502.1(IN)
N19085595: C547.1 R539.2 U13.U23(REFCLK1LN)
N19085617: C546.1 R538.2 U13.U22(REFCLK1LP)
N19102913: C524.1 FB500.2 U504.1(OE) U504.6(VCC)
N19122670: C44.1 U13.AD29(GXB_RX_L0N)
N19122700: C43.1 U13.AD30(GXB_RX_L0P)
N19122796: C42.1 U13.AB29(GXB_RX_L1N)
N19122799: C41.1 U13.AB30(GXB_RX_L1P)
N19122886: C40.1 U13.Y29(GXB_RX_L2N)
N19122889: C39.1 U13.Y30(GXB_RX_L2P)
N19122892: C38.1 U13.V29(GXB_RX_L3N)
N19122895: C37.1 U13.V30(GXB_RX_L3P)
N19122978: C36.1 U13.T29(GXB_RX_L4N)
N19122981: C35.1 U13.T30(GXB_RX_L4P)
N19122984: C34.1 U13.P29(GXB_RX_L5N)
N19122987: C33.1 U13.P30(GXB_RX_L5P)
N19123070: C30.1 U13.K29(GXB_RX_L7N)
N19123073: C29.1 U13.K30(GXB_RX_L7P)
N19123076: C32.1 U13.M29(GXB_RX_L6N)
N19123079: C31.1 U13.M30(GXB_RX_L6P)
N19676306: R190.2 R193.2 U13.AG6(IO_4A)
N19676381: R191.2 R192.2 U13.AF6(IO_4A)
N19774319: R746.1 U514.3(SSC_SEL1)
N19774321: R745.1 U514.2(SSC_SEL0)
N19774337: R747.1 U514.6(OUT)
N19774360: U514.1(Xin) Y1.1
N19774376: U514.8(Xout) Y1.3
N20987908: D10.1(CATHODE) Q4.D
N20987909: D10.2(ANODE) R82.1

Not connected (* = marked no-connect by the designer): J9 7* 9* 11* 12* 23*; J21 6* 7* 8*; U5 1(~{OE})*; U13 AA27(GXB_TX_L1N)* AA28(GXB_TX_L1P)* AC27(GXB_TX_L0N)* AC28(GXB_TX_L0P)* AH30(AS_DATA3_3A_AH30/DATA3)* AJ30(AS_DATA2_3A_AJ30/DATA2)* J27(GXB_TX_L7N)* J28(GXB_TX_L7P)* L27(GXB_TX_L6N)* L28(GXB_TX_L6P)* N27(GXB_TX_L5N)* N28(GXB_TX_L5P)* R27(GXB_TX_L4N)* R28(GXB_TX_L4P)* U27(GXB_TX_L3N)* U28(GXB_TX_L3P)* W27(GXB_TX_L2N)* W28(GXB_TX_L2P)*; U504 2(NC)*

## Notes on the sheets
sheet 28
- Secondary DLPC4420 P1P1V Bypass Capacitors
- Secondary DLPC4420 P1P8V LVDS Bypass Capacitors
- Secondary DLPC4420 P1P8V DRAM Bypass Capacitors
- Secondary DLPC4420 P3P3V Bypass Capacitors
- Secondary
- Secondary Controller Power and Bypass Capacitors
- (C) COPYRIGHT 2023
         Texas Instruments
        All Rights Reserved
sheet 29
- (C) COPYRIGHT 2023
         Texas Instruments
        All Rights Reserved
sheet 30
- If front-end board needs to be supplied with 5V from
  formatter board, install J11
  Default: Not Installed
- J32 Vx1 Swap PN
  Installed: Not Swapping P and N's (Default)
  Not Installed: Swapping P and N's
- J33 Vx1 Swap Order
  Installed: Not Bit Order Swapping (Default)
  Not Installed: Bit Order Swapping
- CCA MOUNTING HOLES
- FPGA - Front-End I/F
- (C) COPYRIGHT 2023
         Texas Instruments
        All Rights Reserved
sheet 31
- FPGA - Video I/F
- (C) COPYRIGHT 2023
         Texas Instruments
        All Rights Reserved
sheet 32
- FPGA - DDR3 Interface
- (C) COPYRIGHT 2023
         Texas Instruments
        All Rights Reserved
sheet 33
- D
- FDV303N
- G
- S
- Switch to allow ASIC to reprogram the FPGA
  bitstream. When IN (PROG_FLASH_IN) is low ASIC
  can reprogram the flash.
- Note: MSEL[4:0] = 10011
  for AS mode, standard POR delay
- RESET PUSH BUTTON
- Actuator Board Interface
- FPGA - Programming and Test Mux
- (C) COPYRIGHT 2023
         Texas Instruments
        All Rights Reserved
